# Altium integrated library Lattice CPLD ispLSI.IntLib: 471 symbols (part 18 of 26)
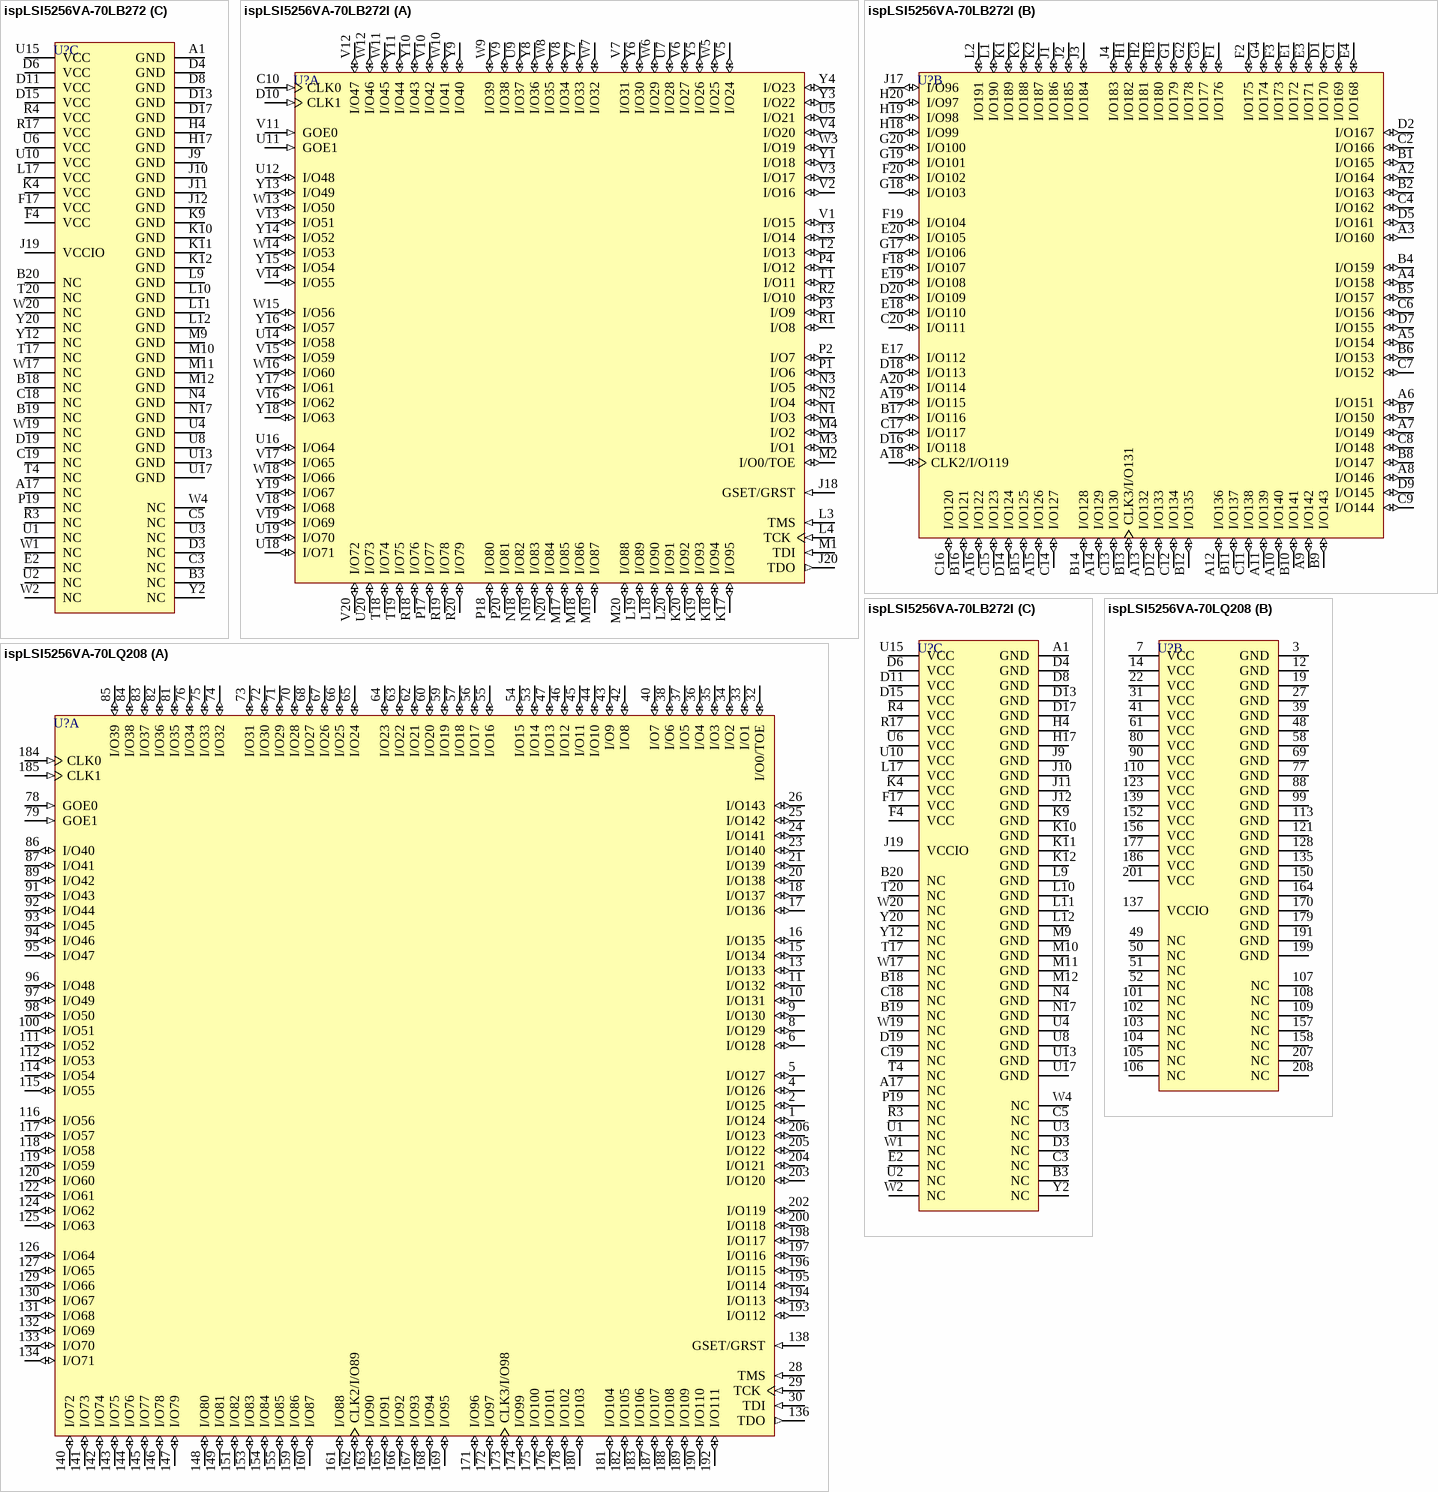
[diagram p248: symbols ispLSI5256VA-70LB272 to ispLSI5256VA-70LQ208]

## ispLSI5256VA-70LB272
designator U?
In-System Programmable 3.3V SuperWIDE High Density PLD
footprint BGA272 (BGA, 272-Leads, Body 27x27mm, Pitch 1.27mm)
3D model 5256VA-BGA272 (272-Ball Ball Grid Array (BGA272))
part A pins: C10 CLK0 (in), D10 CLK1 (in), J18 GSET/GRST (in), J20 TDO (out), K17 I/O95 (io), K18 I/O94 (io), K19 I/O93 (io), K20 I/O92 (io), L3 TMS (in), L4 TCK (in), L18 I/O90 (io), L19 I/O89 (io), L20 I/O91 (io), M1 TDI (in), M2 I/O0/TOE (io), M3 I/O1 (io), M4 I/O2 (io), M17 I/O85 (io), M18 I/O86 (io), M19 I/O87 (io), M20 I/O88 (io), N1 I/O3 (io), N2 I/O4 (io), N3 I/O5 (io), N18 I/O82 (io), N19 I/O83 (io), N20 I/O84 (io), P1 I/O6 (io), P2 I/O7 (io), P3 I/O9 (io), P4 I/O12 (io), P17 I/O77 (io), P18 I/O80 (io), P20 I/O81 (io), R1 I/O8 (io), R2 I/O10 (io), R18 I/O76 (io), R19 I/O78 (io), R20 I/O79 (io), T1 I/O11 (io), T2 I/O13 (io), T3 I/O14 (io), T18 I/O74 (io), T19 I/O75 (io), U5 I/O21 (io), U7 I/O28 (io), U9 I/O37 (io), U11 GOE1 (in), U12 I/O48 (io), U14 I/O58 (io), U16 I/O64 (io), U18 I/O71 (io), U19 I/O70 (io), U20 I/O73 (io), V1 I/O15 (io), V2 I/O16 (io), V3 I/O17 (io), V4 I/O20 (io), V5 I/O24 (io), V6 I/O27 (io), V7 I/O31 (io), V8 I/O34 (io), V9 I/O38 (io), V10 I/O42 (io), V11 GOE0 (in), V12 I/O47 (io), V13 I/O51 (io), V14 I/O55 (io), V15 I/O59 (io), V16 I/O62 (io), V17 I/O65 (io), V18 I/O68 (io), V19 I/O69 (io), V20 I/O72 (io), W3 I/O19 (io), W5 I/O25 (io), W6 I/O29 (io), W7 I/O32 (io), W8 I/O35 (io), W9 I/O39 (io), W10 I/O41 (io), W11 I/O45 (io), W12 I/O46 (io), W13 I/O50 (io), W14 I/O53 (io), W15 I/O56 (io), W16 I/O60 (io), W18 I/O66 (io), Y1 I/O18 (io), Y3 I/O22 (io), Y4 I/O23 (io), Y5 I/O26 (io), Y6 I/O30 (io), Y7 I/O33 (io), Y8 I/O36 (io), Y9 I/O40 (io), Y10 I/O43 (io), Y11 I/O44 (io), Y13 I/O49 (io), Y14 I/O52 (io), Y15 I/O54 (io), Y16 I/O57 (io), Y17 I/O61 (io), Y18 I/O63 (io), Y19 I/O67 (io)
part B pins: A2 I/O164 (io), A3 I/O160 (io), A4 I/O158 (io), A5 I/O154 (io), A6 I/O151 (io), A7 I/O149 (io), A8 I/O146 (io), A9 I/O142 (io), A10 I/O140 (io), A11 I/O139 (io), A12 I/O136 (io), A13 I/O132 (io), A14 I/O129 (io), A15 I/O126 (io), A16 I/O122 (io), A18 CLK2/I/O119 (io), A19 I/O115 (io), A20 I/O114 (io), B1 I/O165 (io), B2 I/O163 (io), B4 I/O159 (io), B5 I/O157 (io), B6 I/O153 (io), B7 I/O150 (io), B8 I/O147 (io), B9 I/O143 (io), B10 I/O141 (io), B11 I/O137 (io), B12 I/O135 (io), B13 CLK3/I/O131 (io), B14 I/O128 (io), B15 I/O125 (io), B16 I/O121 (io), B17 I/O116 (io), C1 I/O169 (io), C2 I/O166 (io), C4 I/O162 (io), C6 I/O156 (io), C7 I/O152 (io), C8 I/O148 (io), C9 I/O144 (io), C11 I/O138 (io), C12 I/O134 (io), C13 I/O130 (io), C14 I/O127 (io), C15 I/O123 (io), C16 I/O120 (io), C17 I/O117 (io), C20 I/O111 (io), D1 I/O170 (io), D2 I/O167 (io), D5 I/O161 (io), D7 I/O155 (io), D9 I/O145 (io), D12 I/O133 (io), D14 I/O124 (io), D16 I/O118 (io), D18 I/O113 (io), D20 I/O109 (io), E1 I/O172 (io), E3 I/O171 (io), E4 I/O168 (io), E17 I/O112 (io), E18 I/O110 (io), E19 I/O108 (io), E20 I/O105 (io), F1 I/O176 (io), F2 I/O175 (io), F3 I/O173 (io), F18 I/O107 (io), F19 I/O104 (io), F20 I/O102 (io), G1 I/O179 (io), G2 I/O178 (io), G3 I/O177 (io), G4 I/O174 (io), G17 I/O106 (io), G18 I/O103 (io), G19 I/O101 (io), G20 I/O100 (io), H1 I/O182 (io), H2 I/O181 (io), H3 I/O180 (io), H18 I/O99 (io), H19 I/O98 (io), H20 I/O97 (io), J1 I/O186 (io), J2 I/O185 (io), J3 I/O184 (io), J4 I/O183 (io), J17 I/O96 (io), K1 I/O189 (io), K2 I/O187 (io), K3 I/O188 (io), L1 I/O190 (io), L2 I/O191 (io)
part C pins: A1 GND (power), A17 NC, B3 NC, B18 NC, B19 NC, B20 NC, C3 NC, C5 NC, C18 NC, C19 NC, D3 NC, D4 GND (power), D6 VCC (power), D8 GND (power), D11 VCC (power), D13 GND (power), D15 VCC (power), D17 GND (power), D19 NC, E2 NC, F4 VCC (power), F17 VCC (power), H4 GND (power), H17 GND (power), J9 GND (power), J10 GND (power), J11 GND (power), J12 GND (power), J19 VCCIO (power), K4 VCC (power), K9 GND (power), K10 GND (power), K11 GND (power), K12 GND (power), L9 GND (power), L10 GND (power), L11 GND (power), L12 GND (power), L17 VCC (power), M9 GND (power), M10 GND (power), M11 GND (power), M12 GND (power), N4 GND (power), N17 GND (power), P19 NC, R3 NC, R4 VCC (power), R17 VCC (power), T4 NC, T17 NC, T20 NC, U1 NC, U2 NC, U3 NC, U4 GND (power), U6 VCC (power), U8 GND (power), U10 VCC (power), U13 GND (power), U15 VCC (power), U17 GND (power), W1 NC, W2 NC, W4 NC, W17 NC, W19 NC, W20 NC, Y2 NC, Y12 NC, Y20 NC

## ispLSI5256VA-70LB272I
designator U?
In-System Programmable 3.3V SuperWIDE High Density PLD
footprint BGA272 (BGA, 272-Leads, Body 27x27mm, Pitch 1.27mm)
3D model 5256VA-BGA272 (272-Ball Ball Grid Array (BGA272))
part A pins: C10 CLK0 (in), D10 CLK1 (in), J18 GSET/GRST (in), J20 TDO (out), K17 I/O95 (io), K18 I/O94 (io), K19 I/O93 (io), K20 I/O92 (io), L3 TMS (in), L4 TCK (in), L18 I/O90 (io), L19 I/O89 (io), L20 I/O91 (io), M1 TDI (in), M2 I/O0/TOE (io), M3 I/O1 (io), M4 I/O2 (io), M17 I/O85 (io), M18 I/O86 (io), M19 I/O87 (io), M20 I/O88 (io), N1 I/O3 (io), N2 I/O4 (io), N3 I/O5 (io), N18 I/O82 (io), N19 I/O83 (io), N20 I/O84 (io), P1 I/O6 (io), P2 I/O7 (io), P3 I/O9 (io), P4 I/O12 (io), P17 I/O77 (io), P18 I/O80 (io), P20 I/O81 (io), R1 I/O8 (io), R2 I/O10 (io), R18 I/O76 (io), R19 I/O78 (io), R20 I/O79 (io), T1 I/O11 (io), T2 I/O13 (io), T3 I/O14 (io), T18 I/O74 (io), T19 I/O75 (io), U5 I/O21 (io), U7 I/O28 (io), U9 I/O37 (io), U11 GOE1 (in), U12 I/O48 (io), U14 I/O58 (io), U16 I/O64 (io), U18 I/O71 (io), U19 I/O70 (io), U20 I/O73 (io), V1 I/O15 (io), V2 I/O16 (io), V3 I/O17 (io), V4 I/O20 (io), V5 I/O24 (io), V6 I/O27 (io), V7 I/O31 (io), V8 I/O34 (io), V9 I/O38 (io), V10 I/O42 (io), V11 GOE0 (in), V12 I/O47 (io), V13 I/O51 (io), V14 I/O55 (io), V15 I/O59 (io), V16 I/O62 (io), V17 I/O65 (io), V18 I/O68 (io), V19 I/O69 (io), V20 I/O72 (io), W3 I/O19 (io), W5 I/O25 (io), W6 I/O29 (io), W7 I/O32 (io), W8 I/O35 (io), W9 I/O39 (io), W10 I/O41 (io), W11 I/O45 (io), W12 I/O46 (io), W13 I/O50 (io), W14 I/O53 (io), W15 I/O56 (io), W16 I/O60 (io), W18 I/O66 (io), Y1 I/O18 (io), Y3 I/O22 (io), Y4 I/O23 (io), Y5 I/O26 (io), Y6 I/O30 (io), Y7 I/O33 (io), Y8 I/O36 (io), Y9 I/O40 (io), Y10 I/O43 (io), Y11 I/O44 (io), Y13 I/O49 (io), Y14 I/O52 (io), Y15 I/O54 (io), Y16 I/O57 (io), Y17 I/O61 (io), Y18 I/O63 (io), Y19 I/O67 (io)
part B pins: A2 I/O164 (io), A3 I/O160 (io), A4 I/O158 (io), A5 I/O154 (io), A6 I/O151 (io), A7 I/O149 (io), A8 I/O146 (io), A9 I/O142 (io), A10 I/O140 (io), A11 I/O139 (io), A12 I/O136 (io), A13 I/O132 (io), A14 I/O129 (io), A15 I/O126 (io), A16 I/O122 (io), A18 CLK2/I/O119 (io), A19 I/O115 (io), A20 I/O114 (io), B1 I/O165 (io), B2 I/O163 (io), B4 I/O159 (io), B5 I/O157 (io), B6 I/O153 (io), B7 I/O150 (io), B8 I/O147 (io), B9 I/O143 (io), B10 I/O141 (io), B11 I/O137 (io), B12 I/O135 (io), B13 CLK3/I/O131 (io), B14 I/O128 (io), B15 I/O125 (io), B16 I/O121 (io), B17 I/O116 (io), C1 I/O169 (io), C2 I/O166 (io), C4 I/O162 (io), C6 I/O156 (io), C7 I/O152 (io), C8 I/O148 (io), C9 I/O144 (io), C11 I/O138 (io), C12 I/O134 (io), C13 I/O130 (io), C14 I/O127 (io), C15 I/O123 (io), C16 I/O120 (io), C17 I/O117 (io), C20 I/O111 (io), D1 I/O170 (io), D2 I/O167 (io), D5 I/O161 (io), D7 I/O155 (io), D9 I/O145 (io), D12 I/O133 (io), D14 I/O124 (io), D16 I/O118 (io), D18 I/O113 (io), D20 I/O109 (io), E1 I/O172 (io), E3 I/O171 (io), E4 I/O168 (io), E17 I/O112 (io), E18 I/O110 (io), E19 I/O108 (io), E20 I/O105 (io), F1 I/O176 (io), F2 I/O175 (io), F3 I/O173 (io), F18 I/O107 (io), F19 I/O104 (io), F20 I/O102 (io), G1 I/O179 (io), G2 I/O178 (io), G3 I/O177 (io), G4 I/O174 (io), G17 I/O106 (io), G18 I/O103 (io), G19 I/O101 (io), G20 I/O100 (io), H1 I/O182 (io), H2 I/O181 (io), H3 I/O180 (io), H18 I/O99 (io), H19 I/O98 (io), H20 I/O97 (io), J1 I/O186 (io), J2 I/O185 (io), J3 I/O184 (io), J4 I/O183 (io), J17 I/O96 (io), K1 I/O189 (io), K2 I/O187 (io), K3 I/O188 (io), L1 I/O190 (io), L2 I/O191 (io)
part C pins: A1 GND (power), A17 NC, B3 NC, B18 NC, B19 NC, B20 NC, C3 NC, C5 NC, C18 NC, C19 NC, D3 NC, D4 GND (power), D6 VCC (power), D8 GND (power), D11 VCC (power), D13 GND (power), D15 VCC (power), D17 GND (power), D19 NC, E2 NC, F4 VCC (power), F17 VCC (power), H4 GND (power), H17 GND (power), J9 GND (power), J10 GND (power), J11 GND (power), J12 GND (power), J19 VCCIO (power), K4 VCC (power), K9 GND (power), K10 GND (power), K11 GND (power), K12 GND (power), L9 GND (power), L10 GND (power), L11 GND (power), L12 GND (power), L17 VCC (power), M9 GND (power), M10 GND (power), M11 GND (power), M12 GND (power), N4 GND (power), N17 GND (power), P19 NC, R3 NC, R4 VCC (power), R17 VCC (power), T4 NC, T17 NC, T20 NC, U1 NC, U2 NC, U3 NC, U4 GND (power), U6 VCC (power), U8 GND (power), U10 VCC (power), U13 GND (power), U15 VCC (power), U17 GND (power), W1 NC, W2 NC, W4 NC, W17 NC, W19 NC, W20 NC, Y2 NC, Y12 NC, Y20 NC

## ispLSI5256VA-70LQ208
designator U?
In-System Programmable 3.3V SuperWIDE High Density PLD
footprint PQFP208_N (Shrink QFP, 208-Leads, Body 28x28mm, Pitch 0.5mm, IPC Medium Density)
footprint PQFP208_L (Shrink QFP, 208-Leads, Body 28x28mm, Pitch 0.5mm, IPC High Density)
footprint PQFP208_M (Shrink QFP, 208-Leads, Body 28x28mm, Pitch 0.5mm, IPC Low Density)
3D model 5256VA-PQFP208 (208-Pin Plastic Quad Flat Pack (PQFP208))
part A pins: 1 I/O124 (io), 2 I/O125 (io), 4 I/O126 (io), 5 I/O127 (io), 6 I/O128 (io), 8 I/O129 (io), 9 I/O130 (io), 10 I/O131 (io), 11 I/O132 (io), 13 I/O133 (io), 15 I/O134 (io), 16 I/O135 (io), 17 I/O136 (io), 18 I/O137 (io), 20 I/O138 (io), 21 I/O139 (io), 23 I/O140 (io), 24 I/O141 (io), 25 I/O142 (io), 26 I/O143 (io), 28 TMS (in), 29 TCK (in), 30 TDI (in), 32 I/O0/TOE (io), 33 I/O1 (io), 34 I/O2 (io), 35 I/O3 (io), 36 I/O4 (io), 37 I/O5 (io), 38 I/O6 (io), 40 I/O7 (io), 42 I/O8 (io), 43 I/O9 (io), 44 I/O10 (io), 45 I/O11 (io), 46 I/O12 (io), 47 I/O13 (io), 53 I/O14 (io), 54 I/O15 (io), 55 I/O16 (io), 56 I/O17 (io), 57 I/O18 (io), 59 I/O19 (io), 60 I/O20 (io), 62 I/O21 (io), 63 I/O22 (io), 64 I/O23 (io), 65 I/O24 (io), 66 I/O25 (io), 67 I/O26 (io), 68 I/O27 (io), 70 I/O28 (io), 71 I/O29 (io), 72 I/O30 (io), 73 I/O31 (io), 74 I/O32 (io), 75 I/O33 (io), 76 I/O34 (io), 78 GOE0 (in), 79 GOE1 (in), 81 I/O35 (io), 82 I/O36 (io), 83 I/O37 (io), 84 I/O38 (io), 85 I/O39 (io), 86 I/O40 (io), 87 I/O41 (io), 89 I/O42 (io), 91 I/O43 (io), 92 I/O44 (io), 93 I/O45 (io), 94 I/O46 (io), 95 I/O47 (io), 96 I/O48 (io), 97 I/O49 (io), 98 I/O50 (io), 100 I/O51 (io), 111 I/O52 (io), 112 I/O53 (io), 114 I/O54 (io), 115 I/O55 (io), 116 I/O56 (io), 117 I/O57 (io), 118 I/O58 (io), 119 I/O59 (io), 120 I/O60 (io), 122 I/O61 (io), 124 I/O62 (io), 125 I/O63 (io), 126 I/O64 (io), 127 I/O65 (io), 129 I/O66 (io), 130 I/O67 (io), 131 I/O68 (io), 132 I/O69 (io), 133 I/O70 (io), 134 I/O71 (io), 136 TDO (out), 138 GSET/GRST (in), 140 I/O72 (io), 141 I/O73 (io), 142 I/O74 (io), 143 I/O75 (io), 144 I/O76 (io), 145 I/O77 (io), 146 I/O78 (io), 147 I/O79 (io), 148 I/O80 (io), 149 I/O81 (io), 151 I/O82 (io), 153 I/O83 (io), 154 I/O84 (io), 155 I/O85 (io), 159 I/O86 (io), 160 I/O87 (io), 161 I/O88 (io), 162 CLK2/I/O89 (io), 163 I/O90 (io), 165 I/O91 (io), 166 I/O92 (io), 167 I/O93 (io), 168 I/O94 (io), 169 I/O95 (io), 171 I/O96 (io), 172 I/O97 (io), 173 CLK3/I/O98 (io), 174 I/O99 (io), 175 I/O100 (io), 176 I/O101 (io), 178 I/O102 (io), 180 I/O103 (io), 181 I/O104 (io), 182 I/O105 (io), 183 I/O106 (io), 184 CLK0 (in), 185 CLK1 (in), 187 I/O107 (io), 188 I/O108 (io), 189 I/O109 (io), 190 I/O110 (io), 192 I/O111 (io), 193 I/O112 (io), 194 I/O113 (io), 195 I/O114 (io), 196 I/O115 (io), 197 I/O116 (io), 198 I/O117 (io), 200 I/O118 (io), 202 I/O119 (io), 203 I/O120 (io), 204 I/O121 (io), 205 I/O122 (io), 206 I/O123 (io)
part B pins: 3 GND (power), 7 VCC (power), 12 GND (power), 14 VCC (power), 19 GND (power), 22 VCC (power), 27 GND (power), 31 VCC (power), 39 GND (power), 41 VCC (power), 48 GND (power), 49 NC, 50 NC, 51 NC, 52 NC, 58 GND (power), 61 VCC (power), 69 GND (power), 77 GND (power), 80 VCC (power), 88 GND (power), 90 VCC (power), 99 GND (power), 101 NC, 102 NC, 103 NC, 104 NC, 105 NC, 106 NC, 107 NC, 108 NC, 109 NC, 110 VCC (power), 113 GND (power), 121 GND (power), 123 VCC (power), 128 GND (power), 135 GND (power), 137 VCCIO (power), 139 VCC (power), 150 GND (power), 152 VCC (power), 156 VCC (power), 157 NC, 158 NC, 164 GND (power), 170 GND (power), 177 VCC (power), 179 GND (power), 186 VCC (power), 191 GND (power), 199 GND (power), 201 VCC (power), 207 NC, 208 NC

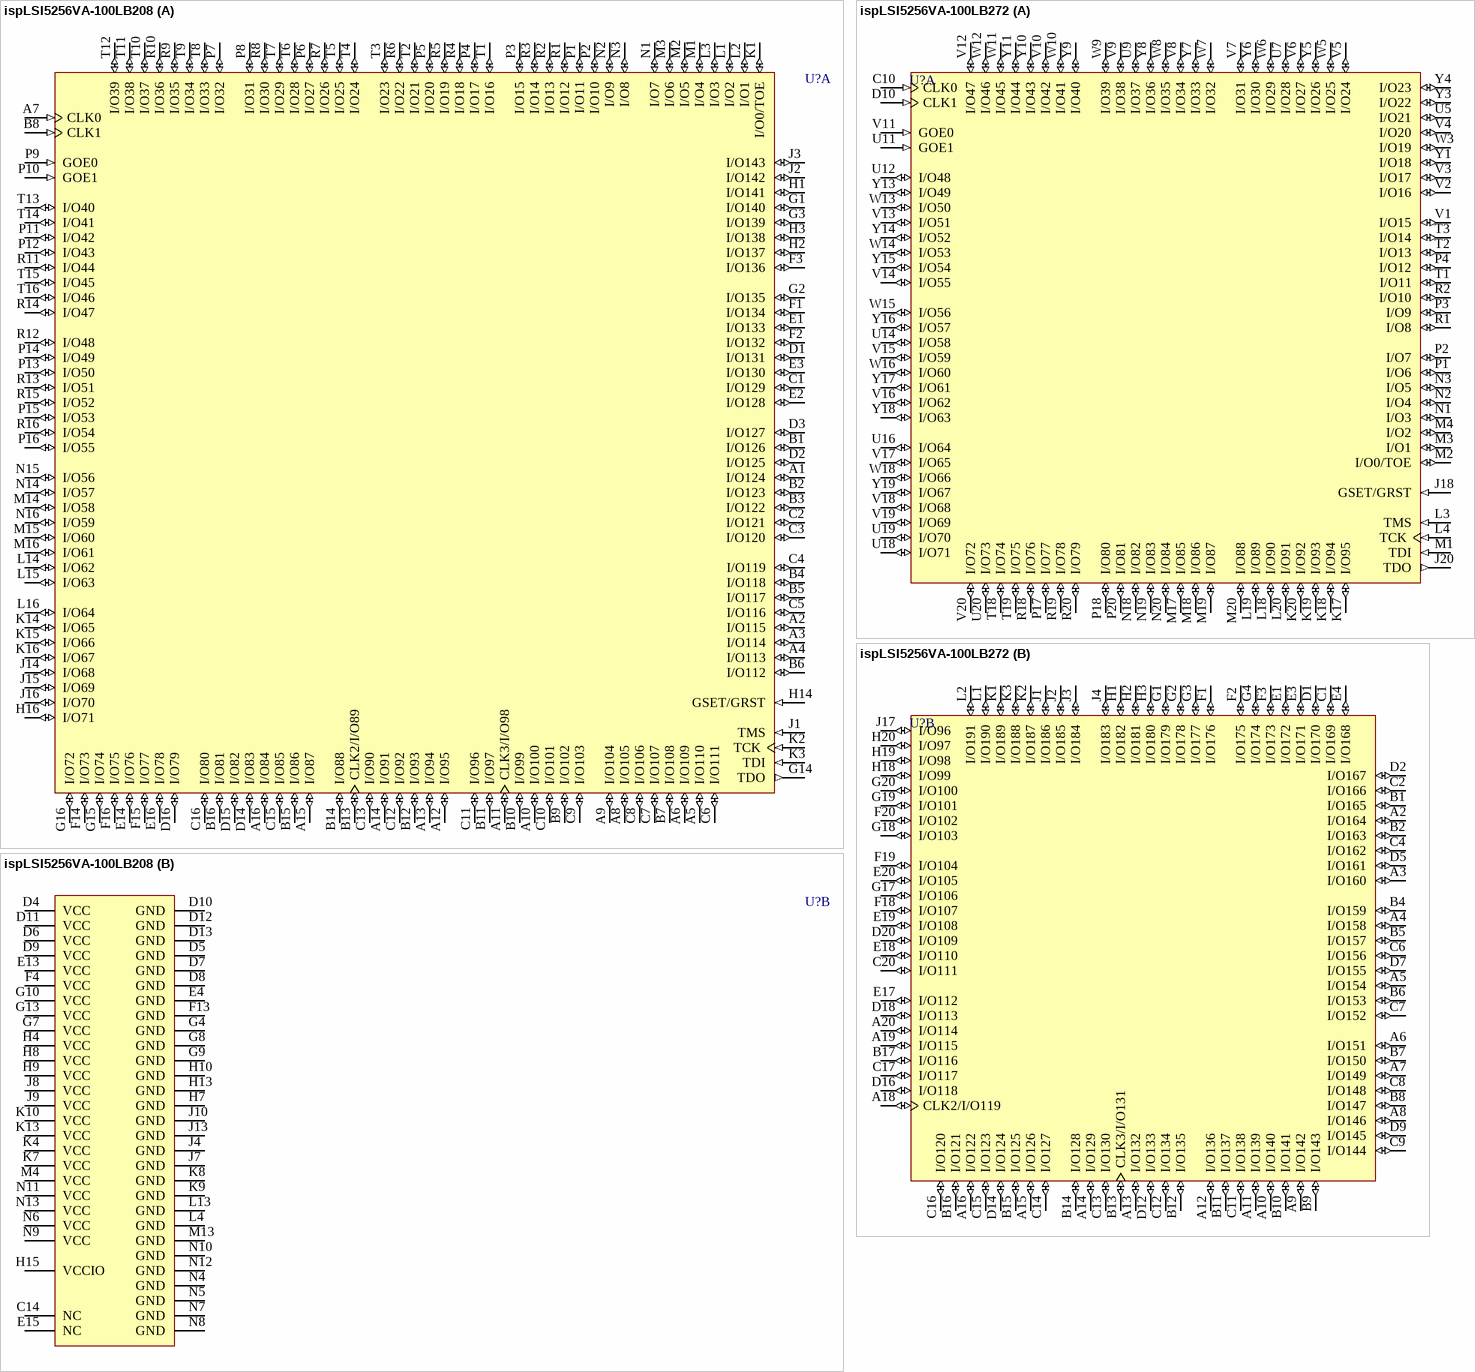
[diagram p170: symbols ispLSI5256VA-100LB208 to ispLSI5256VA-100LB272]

## ispLSI5256VA-100LB208
designator U?
In-System Programmable 3.3V SuperWIDE High Density PLD
footprint fpBGA208 (BGA, 208-Leads, Body 17x17mm, Pitch 1mm)
3D model 5384VA-fpBGA208 (208-Ball Fine Pitch Ball Grid Array (fpBGA208))
part A pins: A1 I/O124 (io), A2 I/O115 (io), A3 I/O114 (io), A4 I/O113 (io), A5 I/O110 (io), A6 I/O109 (io), A7 CLK0 (in), A8 I/O105 (io), A9 I/O104 (io), A10 I/O100 (io), A11 CLK3/I/O98 (io), A12 I/O95 (io), A13 I/O94 (io), A14 I/O91 (io), A15 I/O87 (io), A16 I/O84 (io), B1 I/O126 (io), B2 I/O123 (io), B3 I/O122 (io), B4 I/O118 (io), B5 I/O117 (io), B6 I/O112 (io), B7 I/O108 (io), B8 CLK1 (in), B9 I/O102 (io), B10 I/O99 (io), B11 I/O97 (io), B12 I/O93 (io), B13 CLK2/I/O89 (io), B14 I/O88 (io), B15 I/O86 (io), B16 I/O81 (io), C1 I/O129 (io), C2 I/O121 (io), C3 I/O120 (io), C4 I/O119 (io), C5 I/O116 (io), C6 I/O111 (io), C7 I/O107 (io), C8 I/O106 (io), C9 I/O103 (io), C10 I/O101 (io), C11 I/O96 (io), C12 I/O92 (io), C13 I/O90 (io), C15 I/O85 (io), C16 I/O80 (io), D1 I/O131 (io), D2 I/O125 (io), D3 I/O127 (io), D14 I/O83 (io), D15 I/O82 (io), D16 I/O79 (io), E1 I/O133 (io), E2 I/O128 (io), E3 I/O130 (io), E14 I/O76 (io), E16 I/O78 (io), F1 I/O134 (io), F2 I/O132 (io), F3 I/O136 (io), F14 I/O73 (io), F15 I/O77 (io), F16 I/O75 (io), G1 I/O140 (io), G2 I/O135 (io), G3 I/O139 (io), G14 TDO (out), G15 I/O74 (io), G16 I/O72 (io), H1 I/O141 (io), H2 I/O137 (io), H3 I/O138 (io), H14 GSET/GRST (in), H16 I/O71 (io), J1 TMS (in), J2 I/O142 (io), J3 I/O143 (io), J14 I/O68 (io), J15 I/O69 (io), J16 I/O70 (io), K1 I/O0/TOE (io), K2 TCK (in), K3 TDI (in), K14 I/O65 (io), K15 I/O66 (io), K16 I/O67 (io), L1 I/O2 (io), L2 I/O1 (io), L3 I/O3 (io), L14 I/O62 (io), L15 I/O63 (io), L16 I/O64 (io), M1 I/O4 (io), M2 I/O5 (io), M3 I/O6 (io), M14 I/O58 (io), M15 I/O60 (io), M16 I/O61 (io), N1 I/O7 (io), N2 I/O9 (io), N3 I/O8 (io), N14 I/O57 (io), N15 I/O56 (io), N16 I/O59 (io), P1 I/O11 (io), P2 I/O10 (io), P3 I/O15 (io), P4 I/O17 (io), P5 I/O20 (io), P6 I/O27 (io), P7 I/O32 (io), P8 I/O31 (io), P9 GOE0 (in), P10 GOE1 (in), P11 I/O42 (io), P12 I/O43 (io), P13 I/O50 (io), P14 I/O49 (io), P15 I/O53 (io), P16 I/O55 (io), R1 I/O12 (io), R2 I/O13 (io), R3 I/O14 (io), R4 I/O18 (io), R5 I/O19 (io), R6 I/O22 (io), R7 I/O26 (io), R8 I/O30 (io), R9 I/O35 (io), R10 I/O36 (io), R11 I/O44 (io), R12 I/O48 (io), R13 I/O51 (io), R14 I/O47 (io), R15 I/O52 (io), R16 I/O54 (io), T1 I/O16 (io), T2 I/O21 (io), T3 I/O23 (io), T4 I/O24 (io), T5 I/O25 (io), T6 I/O28 (io), T7 I/O29 (io), T8 I/O33 (io), T9 I/O34 (io), T10 I/O37 (io), T11 I/O38 (io), T12 I/O39 (io), T13 I/O40 (io), T14 I/O41 (io), T15 I/O45 (io), T16 I/O46 (io)
part B pins: C14 NC, D4 VCC (power), D5 GND (power), D6 VCC (power), D7 GND (power), D8 GND (power), D9 VCC (power), D10 GND (power), D11 VCC (power), D12 GND (power), D13 GND (power), E4 GND (power), E13 VCC (power), E15 NC, F4 VCC (power), F13 GND (power), G4 GND (power), G7 VCC (power), G8 GND (power), G9 GND (power), G10 VCC (power), G13 VCC (power), H4 VCC (power), H7 GND (power), H8 VCC (power), H9 VCC (power), H10 GND (power), H13 GND (power), H15 VCCIO (power), J4 GND (power), J7 GND (power), J8 VCC (power), J9 VCC (power), J10 GND (power), J13 GND (power), K4 VCC (power), K7 VCC (power), K8 GND (power), K9 GND (power), K10 VCC (power), K13 VCC (power), L4 GND (power), L13 GND (power), M4 VCC (power), M13 GND (power), N4 GND (power), N5 GND (power), N6 VCC (power), N7 GND (power), N8 GND (power), N9 VCC (power), N10 GND (power), N11 VCC (power), N12 GND (power), N13 VCC (power)

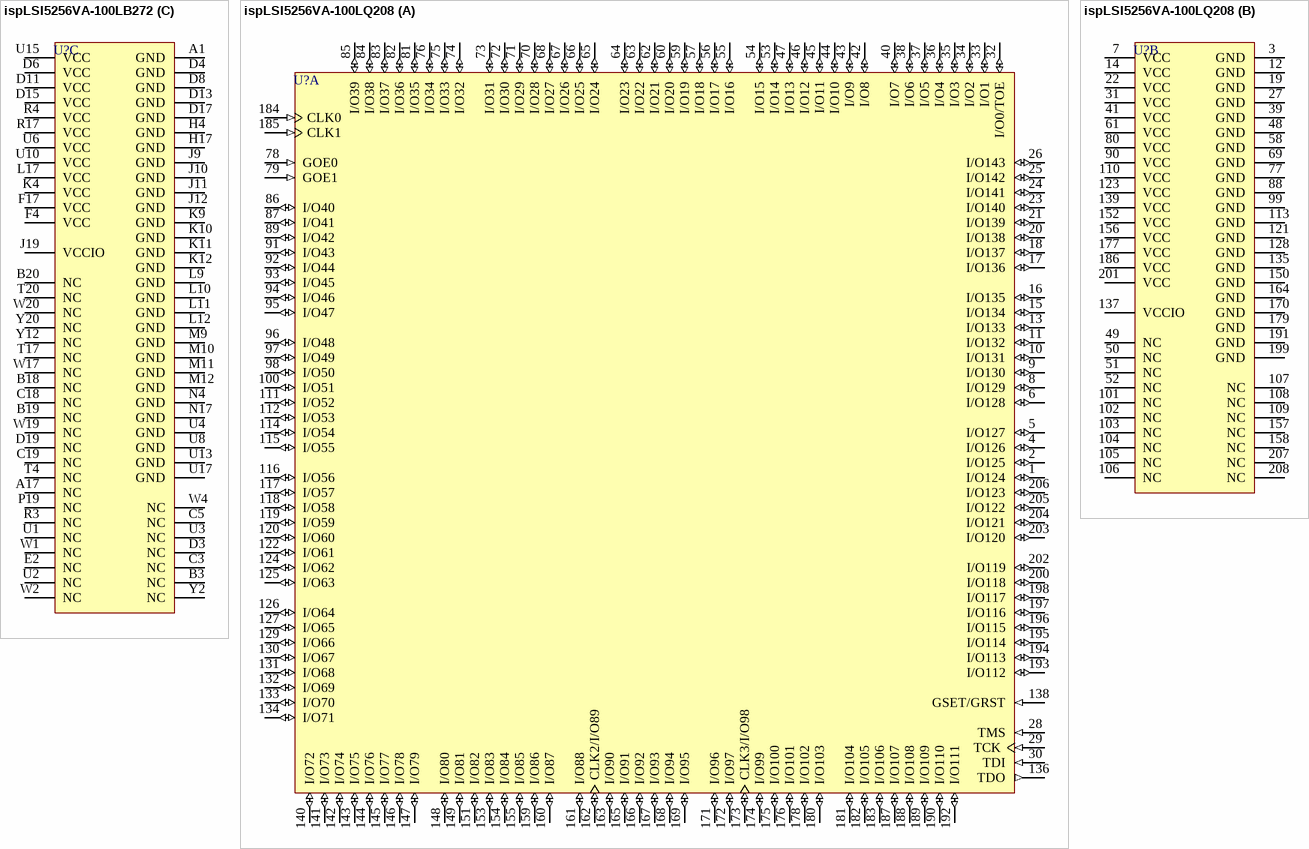
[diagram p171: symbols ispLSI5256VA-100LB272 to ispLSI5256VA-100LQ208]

## ispLSI5256VA-100LB272
designator U?
In-System Programmable 3.3V SuperWIDE High Density PLD
footprint BGA272 (BGA, 272-Leads, Body 27x27mm, Pitch 1.27mm)
3D model 5256VA-BGA272 (272-Ball Ball Grid Array (BGA272))
part A pins: C10 CLK0 (in), D10 CLK1 (in), J18 GSET/GRST (in), J20 TDO (out), K17 I/O95 (io), K18 I/O94 (io), K19 I/O93 (io), K20 I/O92 (io), L3 TMS (in), L4 TCK (in), L18 I/O90 (io), L19 I/O89 (io), L20 I/O91 (io), M1 TDI (in), M2 I/O0/TOE (io), M3 I/O1 (io), M4 I/O2 (io), M17 I/O85 (io), M18 I/O86 (io), M19 I/O87 (io), M20 I/O88 (io), N1 I/O3 (io), N2 I/O4 (io), N3 I/O5 (io), N18 I/O82 (io), N19 I/O83 (io), N20 I/O84 (io), P1 I/O6 (io), P2 I/O7 (io), P3 I/O9 (io), P4 I/O12 (io), P17 I/O77 (io), P18 I/O80 (io), P20 I/O81 (io), R1 I/O8 (io), R2 I/O10 (io), R18 I/O76 (io), R19 I/O78 (io), R20 I/O79 (io), T1 I/O11 (io), T2 I/O13 (io), T3 I/O14 (io), T18 I/O74 (io), T19 I/O75 (io), U5 I/O21 (io), U7 I/O28 (io), U9 I/O37 (io), U11 GOE1 (in), U12 I/O48 (io), U14 I/O58 (io), U16 I/O64 (io), U18 I/O71 (io), U19 I/O70 (io), U20 I/O73 (io), V1 I/O15 (io), V2 I/O16 (io), V3 I/O17 (io), V4 I/O20 (io), V5 I/O24 (io), V6 I/O27 (io), V7 I/O31 (io), V8 I/O34 (io), V9 I/O38 (io), V10 I/O42 (io), V11 GOE0 (in), V12 I/O47 (io), V13 I/O51 (io), V14 I/O55 (io), V15 I/O59 (io), V16 I/O62 (io), V17 I/O65 (io), V18 I/O68 (io), V19 I/O69 (io), V20 I/O72 (io), W3 I/O19 (io), W5 I/O25 (io), W6 I/O29 (io), W7 I/O32 (io), W8 I/O35 (io), W9 I/O39 (io), W10 I/O41 (io), W11 I/O45 (io), W12 I/O46 (io), W13 I/O50 (io), W14 I/O53 (io), W15 I/O56 (io), W16 I/O60 (io), W18 I/O66 (io), Y1 I/O18 (io), Y3 I/O22 (io), Y4 I/O23 (io), Y5 I/O26 (io), Y6 I/O30 (io), Y7 I/O33 (io), Y8 I/O36 (io), Y9 I/O40 (io), Y10 I/O43 (io), Y11 I/O44 (io), Y13 I/O49 (io), Y14 I/O52 (io), Y15 I/O54 (io), Y16 I/O57 (io), Y17 I/O61 (io), Y18 I/O63 (io), Y19 I/O67 (io)
part B pins: A2 I/O164 (io), A3 I/O160 (io), A4 I/O158 (io), A5 I/O154 (io), A6 I/O151 (io), A7 I/O149 (io), A8 I/O146 (io), A9 I/O142 (io), A10 I/O140 (io), A11 I/O139 (io), A12 I/O136 (io), A13 I/O132 (io), A14 I/O129 (io), A15 I/O126 (io), A16 I/O122 (io), A18 CLK2/I/O119 (io), A19 I/O115 (io), A20 I/O114 (io), B1 I/O165 (io), B2 I/O163 (io), B4 I/O159 (io), B5 I/O157 (io), B6 I/O153 (io), B7 I/O150 (io), B8 I/O147 (io), B9 I/O143 (io), B10 I/O141 (io), B11 I/O137 (io), B12 I/O135 (io), B13 CLK3/I/O131 (io), B14 I/O128 (io), B15 I/O125 (io), B16 I/O121 (io), B17 I/O116 (io), C1 I/O169 (io), C2 I/O166 (io), C4 I/O162 (io), C6 I/O156 (io), C7 I/O152 (io), C8 I/O148 (io), C9 I/O144 (io), C11 I/O138 (io), C12 I/O134 (io), C13 I/O130 (io), C14 I/O127 (io), C15 I/O123 (io), C16 I/O120 (io), C17 I/O117 (io), C20 I/O111 (io), D1 I/O170 (io), D2 I/O167 (io), D5 I/O161 (io), D7 I/O155 (io), D9 I/O145 (io), D12 I/O133 (io), D14 I/O124 (io), D16 I/O118 (io), D18 I/O113 (io), D20 I/O109 (io), E1 I/O172 (io), E3 I/O171 (io), E4 I/O168 (io), E17 I/O112 (io), E18 I/O110 (io), E19 I/O108 (io), E20 I/O105 (io), F1 I/O176 (io), F2 I/O175 (io), F3 I/O173 (io), F18 I/O107 (io), F19 I/O104 (io), F20 I/O102 (io), G1 I/O179 (io), G2 I/O178 (io), G3 I/O177 (io), G4 I/O174 (io), G17 I/O106 (io), G18 I/O103 (io), G19 I/O101 (io), G20 I/O100 (io), H1 I/O182 (io), H2 I/O181 (io), H3 I/O180 (io), H18 I/O99 (io), H19 I/O98 (io), H20 I/O97 (io), J1 I/O186 (io), J2 I/O185 (io), J3 I/O184 (io), J4 I/O183 (io), J17 I/O96 (io), K1 I/O189 (io), K2 I/O187 (io), K3 I/O188 (io), L1 I/O190 (io), L2 I/O191 (io)
part C pins: A1 GND (power), A17 NC, B3 NC, B18 NC, B19 NC, B20 NC, C3 NC, C5 NC, C18 NC, C19 NC, D3 NC, D4 GND (power), D6 VCC (power), D8 GND (power), D11 VCC (power), D13 GND (power), D15 VCC (power), D17 GND (power), D19 NC, E2 NC, F4 VCC (power), F17 VCC (power), H4 GND (power), H17 GND (power), J9 GND (power), J10 GND (power), J11 GND (power), J12 GND (power), J19 VCCIO (power), K4 VCC (power), K9 GND (power), K10 GND (power), K11 GND (power), K12 GND (power), L9 GND (power), L10 GND (power), L11 GND (power), L12 GND (power), L17 VCC (power), M9 GND (power), M10 GND (power), M11 GND (power), M12 GND (power), N4 GND (power), N17 GND (power), P19 NC, R3 NC, R4 VCC (power), R17 VCC (power), T4 NC, T17 NC, T20 NC, U1 NC, U2 NC, U3 NC, U4 GND (power), U6 VCC (power), U8 GND (power), U10 VCC (power), U13 GND (power), U15 VCC (power), U17 GND (power), W1 NC, W2 NC, W4 NC, W17 NC, W19 NC, W20 NC, Y2 NC, Y12 NC, Y20 NC

## ispLSI5256VA-100LQ208
designator U?
In-System Programmable 3.3V SuperWIDE High Density PLD
footprint PQFP208_N (Shrink QFP, 208-Leads, Body 28x28mm, Pitch 0.5mm, IPC Medium Density)
footprint PQFP208_L (Shrink QFP, 208-Leads, Body 28x28mm, Pitch 0.5mm, IPC High Density)
footprint PQFP208_M (Shrink QFP, 208-Leads, Body 28x28mm, Pitch 0.5mm, IPC Low Density)
3D model 5256VA-PQFP208 (208-Pin Plastic Quad Flat Pack (PQFP208))
part A pins: 1 I/O124 (io), 2 I/O125 (io), 4 I/O126 (io), 5 I/O127 (io), 6 I/O128 (io), 8 I/O129 (io), 9 I/O130 (io), 10 I/O131 (io), 11 I/O132 (io), 13 I/O133 (io), 15 I/O134 (io), 16 I/O135 (io), 17 I/O136 (io), 18 I/O137 (io), 20 I/O138 (io), 21 I/O139 (io), 23 I/O140 (io), 24 I/O141 (io), 25 I/O142 (io), 26 I/O143 (io), 28 TMS (in), 29 TCK (in), 30 TDI (in), 32 I/O0/TOE (io), 33 I/O1 (io), 34 I/O2 (io), 35 I/O3 (io), 36 I/O4 (io), 37 I/O5 (io), 38 I/O6 (io), 40 I/O7 (io), 42 I/O8 (io), 43 I/O9 (io), 44 I/O10 (io), 45 I/O11 (io), 46 I/O12 (io), 47 I/O13 (io), 53 I/O14 (io), 54 I/O15 (io), 55 I/O16 (io), 56 I/O17 (io), 57 I/O18 (io), 59 I/O19 (io), 60 I/O20 (io), 62 I/O21 (io), 63 I/O22 (io), 64 I/O23 (io), 65 I/O24 (io), 66 I/O25 (io), 67 I/O26 (io), 68 I/O27 (io), 70 I/O28 (io), 71 I/O29 (io), 72 I/O30 (io), 73 I/O31 (io), 74 I/O32 (io), 75 I/O33 (io), 76 I/O34 (io), 78 GOE0 (in), 79 GOE1 (in), 81 I/O35 (io), 82 I/O36 (io), 83 I/O37 (io), 84 I/O38 (io), 85 I/O39 (io), 86 I/O40 (io), 87 I/O41 (io), 89 I/O42 (io), 91 I/O43 (io), 92 I/O44 (io), 93 I/O45 (io), 94 I/O46 (io), 95 I/O47 (io), 96 I/O48 (io), 97 I/O49 (io), 98 I/O50 (io), 100 I/O51 (io), 111 I/O52 (io), 112 I/O53 (io), 114 I/O54 (io), 115 I/O55 (io), 116 I/O56 (io), 117 I/O57 (io), 118 I/O58 (io), 119 I/O59 (io), 120 I/O60 (io), 122 I/O61 (io), 124 I/O62 (io), 125 I/O63 (io), 126 I/O64 (io), 127 I/O65 (io), 129 I/O66 (io), 130 I/O67 (io), 131 I/O68 (io), 132 I/O69 (io), 133 I/O70 (io), 134 I/O71 (io), 136 TDO (out), 138 GSET/GRST (in), 140 I/O72 (io), 141 I/O73 (io), 142 I/O74 (io), 143 I/O75 (io), 144 I/O76 (io), 145 I/O77 (io), 146 I/O78 (io), 147 I/O79 (io), 148 I/O80 (io), 149 I/O81 (io), 151 I/O82 (io), 153 I/O83 (io), 154 I/O84 (io), 155 I/O85 (io), 159 I/O86 (io), 160 I/O87 (io), 161 I/O88 (io), 162 CLK2/I/O89 (io), 163 I/O90 (io), 165 I/O91 (io), 166 I/O92 (io), 167 I/O93 (io), 168 I/O94 (io), 169 I/O95 (io), 171 I/O96 (io), 172 I/O97 (io), 173 CLK3/I/O98 (io), 174 I/O99 (io), 175 I/O100 (io), 176 I/O101 (io), 178 I/O102 (io), 180 I/O103 (io), 181 I/O104 (io), 182 I/O105 (io), 183 I/O106 (io), 184 CLK0 (in), 185 CLK1 (in), 187 I/O107 (io), 188 I/O108 (io), 189 I/O109 (io), 190 I/O110 (io), 192 I/O111 (io), 193 I/O112 (io), 194 I/O113 (io), 195 I/O114 (io), 196 I/O115 (io), 197 I/O116 (io), 198 I/O117 (io), 200 I/O118 (io), 202 I/O119 (io), 203 I/O120 (io), 204 I/O121 (io), 205 I/O122 (io), 206 I/O123 (io)
part B pins: 3 GND (power), 7 VCC (power), 12 GND (power), 14 VCC (power), 19 GND (power), 22 VCC (power), 27 GND (power), 31 VCC (power), 39 GND (power), 41 VCC (power), 48 GND (power), 49 NC, 50 NC, 51 NC, 52 NC, 58 GND (power), 61 VCC (power), 69 GND (power), 77 GND (power), 80 VCC (power), 88 GND (power), 90 VCC (power), 99 GND (power), 101 NC, 102 NC, 103 NC, 104 NC, 105 NC, 106 NC, 107 NC, 108 NC, 109 NC, 110 VCC (power), 113 GND (power), 121 GND (power), 123 VCC (power), 128 GND (power), 135 GND (power), 137 VCCIO (power), 139 VCC (power), 150 GND (power), 152 VCC (power), 156 VCC (power), 157 NC, 158 NC, 164 GND (power), 170 GND (power), 177 VCC (power), 179 GND (power), 186 VCC (power), 191 GND (power), 199 GND (power), 201 VCC (power), 207 NC, 208 NC

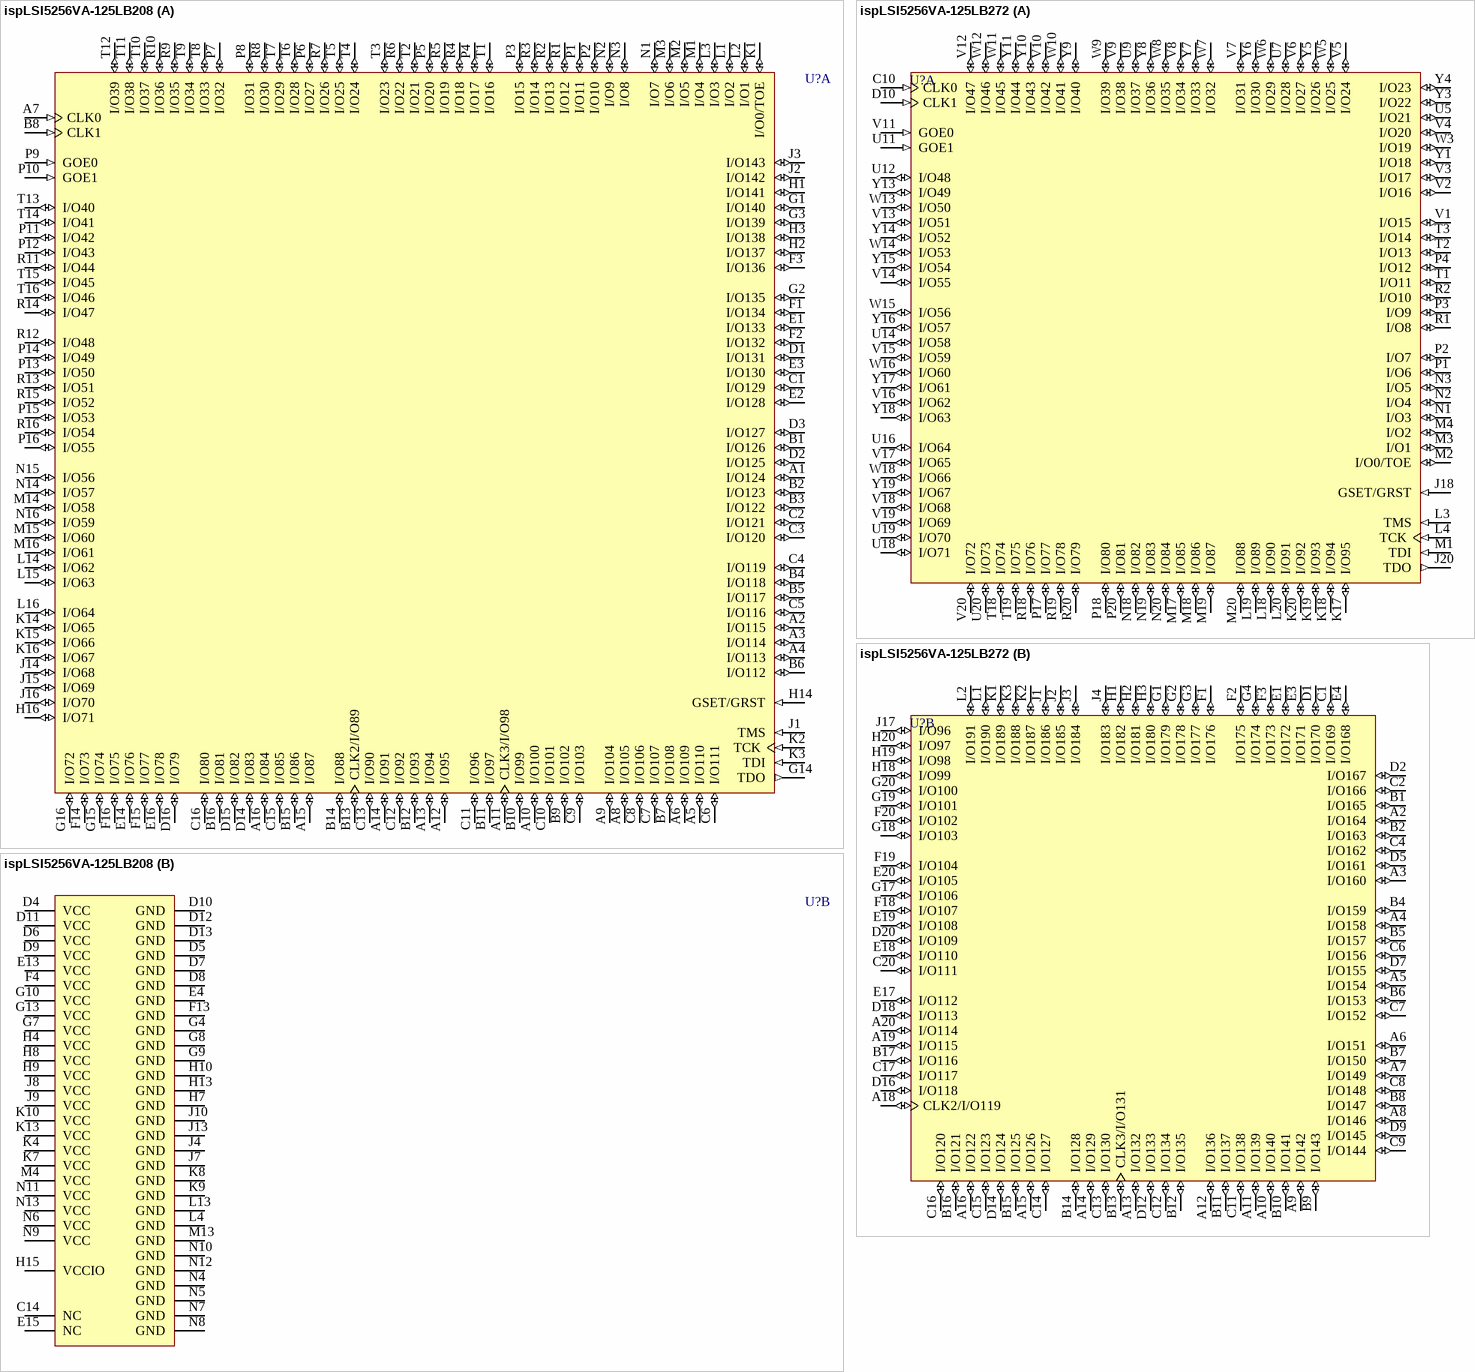
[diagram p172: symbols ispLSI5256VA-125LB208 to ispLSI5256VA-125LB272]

## ispLSI5256VA-125LB208
designator U?
In-System Programmable 3.3V SuperWIDE High Density PLD
footprint fpBGA208 (BGA, 208-Leads, Body 17x17mm, Pitch 1mm)
3D model 5384VA-fpBGA208 (208-Ball Fine Pitch Ball Grid Array (fpBGA208))
part A pins: A1 I/O124 (io), A2 I/O115 (io), A3 I/O114 (io), A4 I/O113 (io), A5 I/O110 (io), A6 I/O109 (io), A7 CLK0 (in), A8 I/O105 (io), A9 I/O104 (io), A10 I/O100 (io), A11 CLK3/I/O98 (io), A12 I/O95 (io), A13 I/O94 (io), A14 I/O91 (io), A15 I/O87 (io), A16 I/O84 (io), B1 I/O126 (io), B2 I/O123 (io), B3 I/O122 (io), B4 I/O118 (io), B5 I/O117 (io), B6 I/O112 (io), B7 I/O108 (io), B8 CLK1 (in), B9 I/O102 (io), B10 I/O99 (io), B11 I/O97 (io), B12 I/O93 (io), B13 CLK2/I/O89 (io), B14 I/O88 (io), B15 I/O86 (io), B16 I/O81 (io), C1 I/O129 (io), C2 I/O121 (io), C3 I/O120 (io), C4 I/O119 (io), C5 I/O116 (io), C6 I/O111 (io), C7 I/O107 (io), C8 I/O106 (io), C9 I/O103 (io), C10 I/O101 (io), C11 I/O96 (io), C12 I/O92 (io), C13 I/O90 (io), C15 I/O85 (io), C16 I/O80 (io), D1 I/O131 (io), D2 I/O125 (io), D3 I/O127 (io), D14 I/O83 (io), D15 I/O82 (io), D16 I/O79 (io), E1 I/O133 (io), E2 I/O128 (io), E3 I/O130 (io), E14 I/O76 (io), E16 I/O78 (io), F1 I/O134 (io), F2 I/O132 (io), F3 I/O136 (io), F14 I/O73 (io), F15 I/O77 (io), F16 I/O75 (io), G1 I/O140 (io), G2 I/O135 (io), G3 I/O139 (io), G14 TDO (out), G15 I/O74 (io), G16 I/O72 (io), H1 I/O141 (io), H2 I/O137 (io), H3 I/O138 (io), H14 GSET/GRST (in), H16 I/O71 (io), J1 TMS (in), J2 I/O142 (io), J3 I/O143 (io), J14 I/O68 (io), J15 I/O69 (io), J16 I/O70 (io), K1 I/O0/TOE (io), K2 TCK (in), K3 TDI (in), K14 I/O65 (io), K15 I/O66 (io), K16 I/O67 (io), L1 I/O2 (io), L2 I/O1 (io), L3 I/O3 (io), L14 I/O62 (io), L15 I/O63 (io), L16 I/O64 (io), M1 I/O4 (io), M2 I/O5 (io), M3 I/O6 (io), M14 I/O58 (io), M15 I/O60 (io), M16 I/O61 (io), N1 I/O7 (io), N2 I/O9 (io), N3 I/O8 (io), N14 I/O57 (io), N15 I/O56 (io), N16 I/O59 (io), P1 I/O11 (io), P2 I/O10 (io), P3 I/O15 (io), P4 I/O17 (io), P5 I/O20 (io), P6 I/O27 (io), P7 I/O32 (io), P8 I/O31 (io), P9 GOE0 (in), P10 GOE1 (in), P11 I/O42 (io), P12 I/O43 (io), P13 I/O50 (io), P14 I/O49 (io), P15 I/O53 (io), P16 I/O55 (io), R1 I/O12 (io), R2 I/O13 (io), R3 I/O14 (io), R4 I/O18 (io), R5 I/O19 (io), R6 I/O22 (io), R7 I/O26 (io), R8 I/O30 (io), R9 I/O35 (io), R10 I/O36 (io), R11 I/O44 (io), R12 I/O48 (io), R13 I/O51 (io), R14 I/O47 (io), R15 I/O52 (io), R16 I/O54 (io), T1 I/O16 (io), T2 I/O21 (io), T3 I/O23 (io), T4 I/O24 (io), T5 I/O25 (io), T6 I/O28 (io), T7 I/O29 (io), T8 I/O33 (io), T9 I/O34 (io), T10 I/O37 (io), T11 I/O38 (io), T12 I/O39 (io), T13 I/O40 (io), T14 I/O41 (io), T15 I/O45 (io), T16 I/O46 (io)
part B pins: C14 NC, D4 VCC (power), D5 GND (power), D6 VCC (power), D7 GND (power), D8 GND (power), D9 VCC (power), D10 GND (power), D11 VCC (power), D12 GND (power), D13 GND (power), E4 GND (power), E13 VCC (power), E15 NC, F4 VCC (power), F13 GND (power), G4 GND (power), G7 VCC (power), G8 GND (power), G9 GND (power), G10 VCC (power), G13 VCC (power), H4 VCC (power), H7 GND (power), H8 VCC (power), H9 VCC (power), H10 GND (power), H13 GND (power), H15 VCCIO (power), J4 GND (power), J7 GND (power), J8 VCC (power), J9 VCC (power), J10 GND (power), J13 GND (power), K4 VCC (power), K7 VCC (power), K8 GND (power), K9 GND (power), K10 VCC (power), K13 VCC (power), L4 GND (power), L13 GND (power), M4 VCC (power), M13 GND (power), N4 GND (power), N5 GND (power), N6 VCC (power), N7 GND (power), N8 GND (power), N9 VCC (power), N10 GND (power), N11 VCC (power), N12 GND (power), N13 VCC (power)

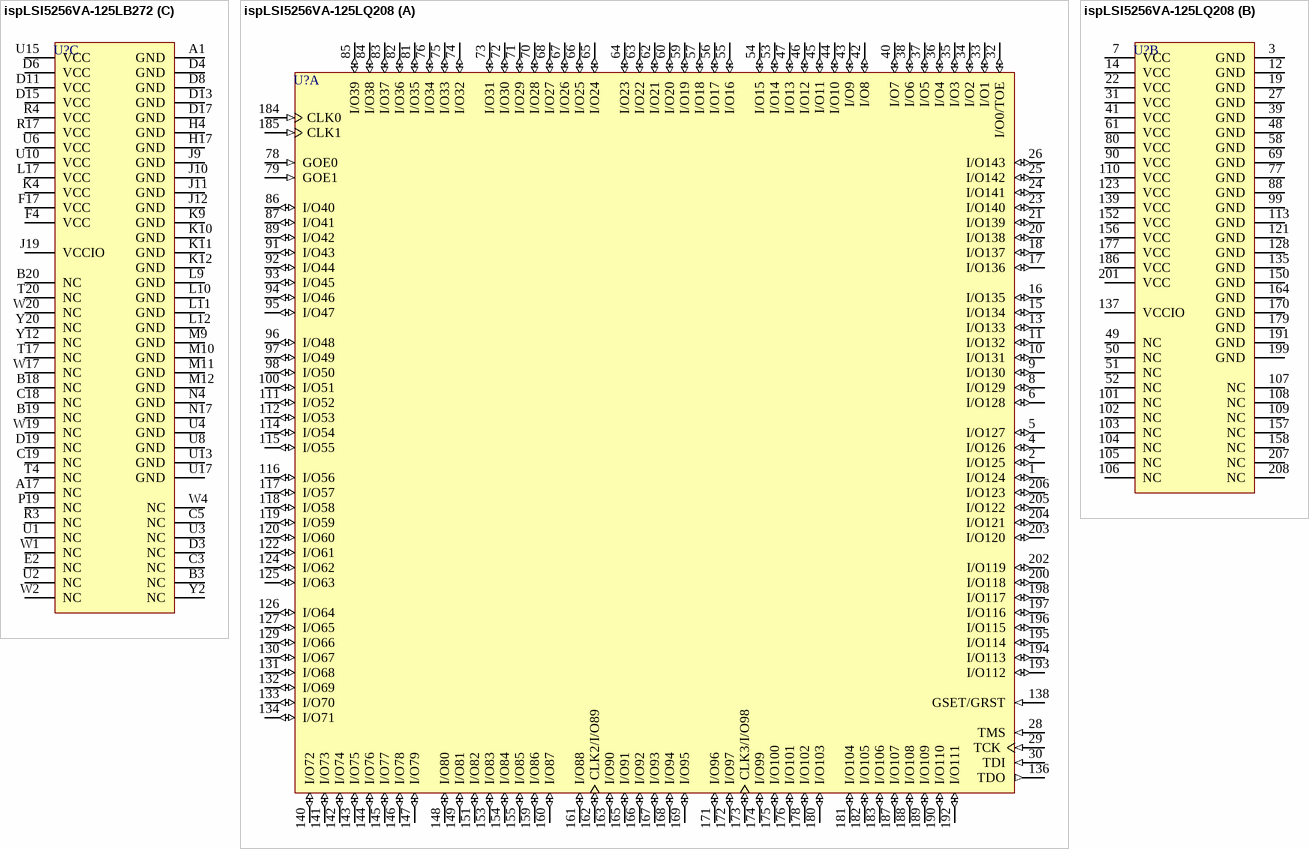
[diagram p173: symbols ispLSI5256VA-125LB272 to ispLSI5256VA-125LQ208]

## ispLSI5256VA-125LB272
designator U?
In-System Programmable 3.3V SuperWIDE High Density PLD
footprint BGA272 (BGA, 272-Leads, Body 27x27mm, Pitch 1.27mm)
3D model 5256VA-BGA272 (272-Ball Ball Grid Array (BGA272))
part A pins: C10 CLK0 (in), D10 CLK1 (in), J18 GSET/GRST (in), J20 TDO (out), K17 I/O95 (io), K18 I/O94 (io), K19 I/O93 (io), K20 I/O92 (io), L3 TMS (in), L4 TCK (in), L18 I/O90 (io), L19 I/O89 (io), L20 I/O91 (io), M1 TDI (in), M2 I/O0/TOE (io), M3 I/O1 (io), M4 I/O2 (io), M17 I/O85 (io), M18 I/O86 (io), M19 I/O87 (io), M20 I/O88 (io), N1 I/O3 (io), N2 I/O4 (io), N3 I/O5 (io), N18 I/O82 (io), N19 I/O83 (io), N20 I/O84 (io), P1 I/O6 (io), P2 I/O7 (io), P3 I/O9 (io), P4 I/O12 (io), P17 I/O77 (io), P18 I/O80 (io), P20 I/O81 (io), R1 I/O8 (io), R2 I/O10 (io), R18 I/O76 (io), R19 I/O78 (io), R20 I/O79 (io), T1 I/O11 (io), T2 I/O13 (io), T3 I/O14 (io), T18 I/O74 (io), T19 I/O75 (io), U5 I/O21 (io), U7 I/O28 (io), U9 I/O37 (io), U11 GOE1 (in), U12 I/O48 (io), U14 I/O58 (io), U16 I/O64 (io), U18 I/O71 (io), U19 I/O70 (io), U20 I/O73 (io), V1 I/O15 (io), V2 I/O16 (io), V3 I/O17 (io), V4 I/O20 (io), V5 I/O24 (io), V6 I/O27 (io), V7 I/O31 (io), V8 I/O34 (io), V9 I/O38 (io), V10 I/O42 (io), V11 GOE0 (in), V12 I/O47 (io), V13 I/O51 (io), V14 I/O55 (io), V15 I/O59 (io), V16 I/O62 (io), V17 I/O65 (io), V18 I/O68 (io), V19 I/O69 (io), V20 I/O72 (io), W3 I/O19 (io), W5 I/O25 (io), W6 I/O29 (io), W7 I/O32 (io), W8 I/O35 (io), W9 I/O39 (io), W10 I/O41 (io), W11 I/O45 (io), W12 I/O46 (io), W13 I/O50 (io), W14 I/O53 (io), W15 I/O56 (io), W16 I/O60 (io), W18 I/O66 (io), Y1 I/O18 (io), Y3 I/O22 (io), Y4 I/O23 (io), Y5 I/O26 (io), Y6 I/O30 (io), Y7 I/O33 (io), Y8 I/O36 (io), Y9 I/O40 (io), Y10 I/O43 (io), Y11 I/O44 (io), Y13 I/O49 (io), Y14 I/O52 (io), Y15 I/O54 (io), Y16 I/O57 (io), Y17 I/O61 (io), Y18 I/O63 (io), Y19 I/O67 (io)
part B pins: A2 I/O164 (io), A3 I/O160 (io), A4 I/O158 (io), A5 I/O154 (io), A6 I/O151 (io), A7 I/O149 (io), A8 I/O146 (io), A9 I/O142 (io), A10 I/O140 (io), A11 I/O139 (io), A12 I/O136 (io), A13 I/O132 (io), A14 I/O129 (io), A15 I/O126 (io), A16 I/O122 (io), A18 CLK2/I/O119 (io), A19 I/O115 (io), A20 I/O114 (io), B1 I/O165 (io), B2 I/O163 (io), B4 I/O159 (io), B5 I/O157 (io), B6 I/O153 (io), B7 I/O150 (io), B8 I/O147 (io), B9 I/O143 (io), B10 I/O141 (io), B11 I/O137 (io), B12 I/O135 (io), B13 CLK3/I/O131 (io), B14 I/O128 (io), B15 I/O125 (io), B16 I/O121 (io), B17 I/O116 (io), C1 I/O169 (io), C2 I/O166 (io), C4 I/O162 (io), C6 I/O156 (io), C7 I/O152 (io), C8 I/O148 (io), C9 I/O144 (io), C11 I/O138 (io), C12 I/O134 (io), C13 I/O130 (io), C14 I/O127 (io), C15 I/O123 (io), C16 I/O120 (io), C17 I/O117 (io), C20 I/O111 (io), D1 I/O170 (io), D2 I/O167 (io), D5 I/O161 (io), D7 I/O155 (io), D9 I/O145 (io), D12 I/O133 (io), D14 I/O124 (io), D16 I/O118 (io), D18 I/O113 (io), D20 I/O109 (io), E1 I/O172 (io), E3 I/O171 (io), E4 I/O168 (io), E17 I/O112 (io), E18 I/O110 (io), E19 I/O108 (io), E20 I/O105 (io), F1 I/O176 (io), F2 I/O175 (io), F3 I/O173 (io), F18 I/O107 (io), F19 I/O104 (io), F20 I/O102 (io), G1 I/O179 (io), G2 I/O178 (io), G3 I/O177 (io), G4 I/O174 (io), G17 I/O106 (io), G18 I/O103 (io), G19 I/O101 (io), G20 I/O100 (io), H1 I/O182 (io), H2 I/O181 (io), H3 I/O180 (io), H18 I/O99 (io), H19 I/O98 (io), H20 I/O97 (io), J1 I/O186 (io), J2 I/O185 (io), J3 I/O184 (io), J4 I/O183 (io), J17 I/O96 (io), K1 I/O189 (io), K2 I/O187 (io), K3 I/O188 (io), L1 I/O190 (io), L2 I/O191 (io)
part C pins: A1 GND (power), A17 NC, B3 NC, B18 NC, B19 NC, B20 NC, C3 NC, C5 NC, C18 NC, C19 NC, D3 NC, D4 GND (power), D6 VCC (power), D8 GND (power), D11 VCC (power), D13 GND (power), D15 VCC (power), D17 GND (power), D19 NC, E2 NC, F4 VCC (power), F17 VCC (power), H4 GND (power), H17 GND (power), J9 GND (power), J10 GND (power), J11 GND (power), J12 GND (power), J19 VCCIO (power), K4 VCC (power), K9 GND (power), K10 GND (power), K11 GND (power), K12 GND (power), L9 GND (power), L10 GND (power), L11 GND (power), L12 GND (power), L17 VCC (power), M9 GND (power), M10 GND (power), M11 GND (power), M12 GND (power), N4 GND (power), N17 GND (power), P19 NC, R3 NC, R4 VCC (power), R17 VCC (power), T4 NC, T17 NC, T20 NC, U1 NC, U2 NC, U3 NC, U4 GND (power), U6 VCC (power), U8 GND (power), U10 VCC (power), U13 GND (power), U15 VCC (power), U17 GND (power), W1 NC, W2 NC, W4 NC, W17 NC, W19 NC, W20 NC, Y2 NC, Y12 NC, Y20 NC

## ispLSI5256VA-125LQ208
designator U?
In-System Programmable 3.3V SuperWIDE High Density PLD
footprint PQFP208_N (Shrink QFP, 208-Leads, Body 28x28mm, Pitch 0.5mm, IPC Medium Density)
footprint PQFP208_L (Shrink QFP, 208-Leads, Body 28x28mm, Pitch 0.5mm, IPC High Density)
footprint PQFP208_M (Shrink QFP, 208-Leads, Body 28x28mm, Pitch 0.5mm, IPC Low Density)
3D model 5256VA-PQFP208 (208-Pin Plastic Quad Flat Pack (PQFP208))
part A pins: 1 I/O124 (io), 2 I/O125 (io), 4 I/O126 (io), 5 I/O127 (io), 6 I/O128 (io), 8 I/O129 (io), 9 I/O130 (io), 10 I/O131 (io), 11 I/O132 (io), 13 I/O133 (io), 15 I/O134 (io), 16 I/O135 (io), 17 I/O136 (io), 18 I/O137 (io), 20 I/O138 (io), 21 I/O139 (io), 23 I/O140 (io), 24 I/O141 (io), 25 I/O142 (io), 26 I/O143 (io), 28 TMS (in), 29 TCK (in), 30 TDI (in), 32 I/O0/TOE (io), 33 I/O1 (io), 34 I/O2 (io), 35 I/O3 (io), 36 I/O4 (io), 37 I/O5 (io), 38 I/O6 (io), 40 I/O7 (io), 42 I/O8 (io), 43 I/O9 (io), 44 I/O10 (io), 45 I/O11 (io), 46 I/O12 (io), 47 I/O13 (io), 53 I/O14 (io), 54 I/O15 (io), 55 I/O16 (io), 56 I/O17 (io), 57 I/O18 (io), 59 I/O19 (io), 60 I/O20 (io), 62 I/O21 (io), 63 I/O22 (io), 64 I/O23 (io), 65 I/O24 (io), 66 I/O25 (io), 67 I/O26 (io), 68 I/O27 (io), 70 I/O28 (io), 71 I/O29 (io), 72 I/O30 (io), 73 I/O31 (io), 74 I/O32 (io), 75 I/O33 (io), 76 I/O34 (io), 78 GOE0 (in), 79 GOE1 (in), 81 I/O35 (io), 82 I/O36 (io), 83 I/O37 (io), 84 I/O38 (io), 85 I/O39 (io), 86 I/O40 (io), 87 I/O41 (io), 89 I/O42 (io), 91 I/O43 (io), 92 I/O44 (io), 93 I/O45 (io), 94 I/O46 (io), 95 I/O47 (io), 96 I/O48 (io), 97 I/O49 (io), 98 I/O50 (io), 100 I/O51 (io), 111 I/O52 (io), 112 I/O53 (io), 114 I/O54 (io), 115 I/O55 (io), 116 I/O56 (io), 117 I/O57 (io), 118 I/O58 (io), 119 I/O59 (io), 120 I/O60 (io), 122 I/O61 (io), 124 I/O62 (io), 125 I/O63 (io), 126 I/O64 (io), 127 I/O65 (io), 129 I/O66 (io), 130 I/O67 (io), 131 I/O68 (io), 132 I/O69 (io), 133 I/O70 (io), 134 I/O71 (io), 136 TDO (out), 138 GSET/GRST (in), 140 I/O72 (io), 141 I/O73 (io), 142 I/O74 (io), 143 I/O75 (io), 144 I/O76 (io), 145 I/O77 (io), 146 I/O78 (io), 147 I/O79 (io), 148 I/O80 (io), 149 I/O81 (io), 151 I/O82 (io), 153 I/O83 (io), 154 I/O84 (io), 155 I/O85 (io), 159 I/O86 (io), 160 I/O87 (io), 161 I/O88 (io), 162 CLK2/I/O89 (io), 163 I/O90 (io), 165 I/O91 (io), 166 I/O92 (io), 167 I/O93 (io), 168 I/O94 (io), 169 I/O95 (io), 171 I/O96 (io), 172 I/O97 (io), 173 CLK3/I/O98 (io), 174 I/O99 (io), 175 I/O100 (io), 176 I/O101 (io), 178 I/O102 (io), 180 I/O103 (io), 181 I/O104 (io), 182 I/O105 (io), 183 I/O106 (io), 184 CLK0 (in), 185 CLK1 (in), 187 I/O107 (io), 188 I/O108 (io), 189 I/O109 (io), 190 I/O110 (io), 192 I/O111 (io), 193 I/O112 (io), 194 I/O113 (io), 195 I/O114 (io), 196 I/O115 (io), 197 I/O116 (io), 198 I/O117 (io), 200 I/O118 (io), 202 I/O119 (io), 203 I/O120 (io), 204 I/O121 (io), 205 I/O122 (io), 206 I/O123 (io)
part B pins: 3 GND (power), 7 VCC (power), 12 GND (power), 14 VCC (power), 19 GND (power), 22 VCC (power), 27 GND (power), 31 VCC (power), 39 GND (power), 41 VCC (power), 48 GND (power), 49 NC, 50 NC, 51 NC, 52 NC, 58 GND (power), 61 VCC (power), 69 GND (power), 77 GND (power), 80 VCC (power), 88 GND (power), 90 VCC (power), 99 GND (power), 101 NC, 102 NC, 103 NC, 104 NC, 105 NC, 106 NC, 107 NC, 108 NC, 109 NC, 110 VCC (power), 113 GND (power), 121 GND (power), 123 VCC (power), 128 GND (power), 135 GND (power), 137 VCCIO (power), 139 VCC (power), 150 GND (power), 152 VCC (power), 156 VCC (power), 157 NC, 158 NC, 164 GND (power), 170 GND (power), 177 VCC (power), 179 GND (power), 186 VCC (power), 191 GND (power), 199 GND (power), 201 VCC (power), 207 NC, 208 NC

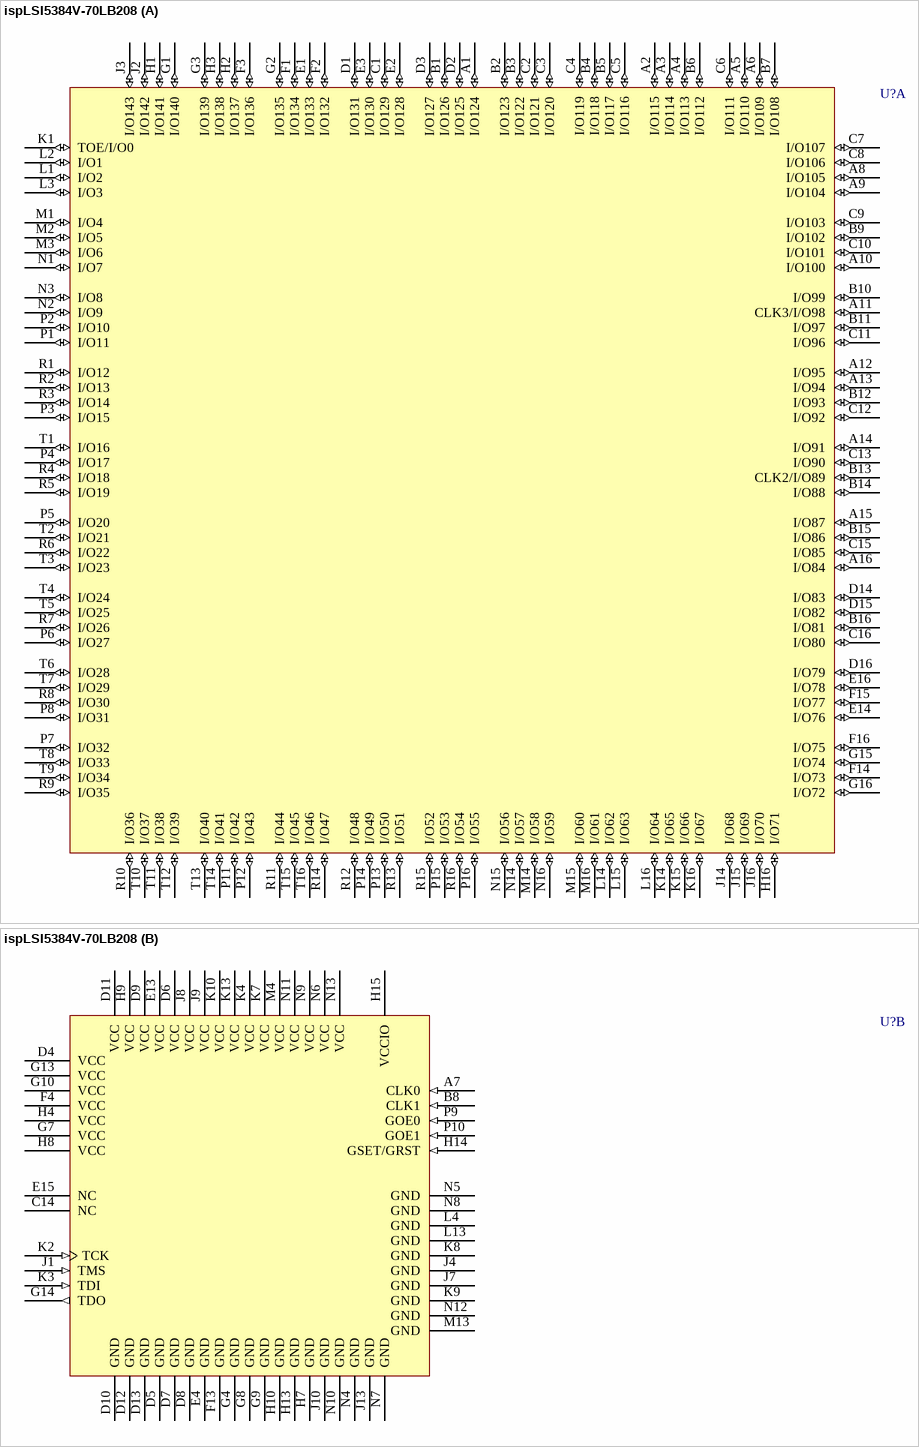
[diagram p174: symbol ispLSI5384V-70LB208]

## ispLSI5384V-70LB208
designator U?
In-System Programmable 3.3V SuperWIDE High-Density PLD; Note: I/O89 is multiplexed with CLK2; I/O98 is multiplexed with CLK3; I/O0 is multiplexed with TOE.
footprint fpBGA208 (BGA, 208-Leads, Body 17x17mm, Pitch 1mm)
3D model 5384V-fpBGA208 (208-Ball Fine Pitch Ball Grid Array (fpBGA208))
part A pins: A1 I/O124 (io), A2 I/O115 (io), A3 I/O114 (io), A4 I/O113 (io), A5 I/O110 (io), A6 I/O109 (io), A8 I/O105 (io), A9 I/O104 (io), A10 I/O100 (io), A11 CLK3/I/O98 (io), A12 I/O95 (io), A13 I/O94 (io), A14 I/O91 (io), A15 I/O87 (io), A16 I/O84 (io), B1 I/O126 (io), B2 I/O123 (io), B3 I/O122 (io), B4 I/O118 (io), B5 I/O117 (io), B6 I/O112 (io), B7 I/O108 (io), B9 I/O102 (io), B10 I/O99 (io), B11 I/O97 (io), B12 I/O93 (io), B13 CLK2/I/O89 (io), B14 I/O88 (io), B15 I/O86 (io), B16 I/O81 (io), C1 I/O129 (io), C2 I/O121 (io), C3 I/O120 (io), C4 I/O119 (io), C5 I/O116 (io), C6 I/O111 (io), C7 I/O107 (io), C8 I/O106 (io), C9 I/O103 (io), C10 I/O101 (io), C11 I/O96 (io), C12 I/O92 (io), C13 I/O90 (io), C15 I/O85 (io), C16 I/O80 (io), D1 I/O131 (io), D2 I/O125 (io), D3 I/O127 (io), D14 I/O83 (io), D15 I/O82 (io), D16 I/O79 (io), E1 I/O133 (io), E2 I/O128 (io), E3 I/O130 (io), E14 I/O76 (io), E16 I/O78 (io), F1 I/O134 (io), F2 I/O132 (io), F3 I/O136 (io), F14 I/O73 (io), F15 I/O77 (io), F16 I/O75 (io), G1 I/O140 (io), G2 I/O135 (io), G3 I/O139 (io), G15 I/O74 (io), G16 I/O72 (io), H1 I/O141 (io), H2 I/O137 (io), H3 I/O138 (io), H16 I/O71 (io), J2 I/O142 (io), J3 I/O143 (io), J14 I/O68 (io), J15 I/O69 (io), J16 I/O70 (io), K1 TOE/I/O0 (io), K14 I/O65 (io), K15 I/O66 (io), K16 I/O67 (io), L1 I/O2 (io), L2 I/O1 (io), L3 I/O3 (io), L14 I/O62 (io), L15 I/O63 (io), L16 I/O64 (io), M1 I/O4 (io), M2 I/O5 (io), M3 I/O6 (io), M14 I/O58 (io), M15 I/O60 (io), M16 I/O61 (io), N1 I/O7 (io), N2 I/O9 (io), N3 I/O8 (io), N14 I/O57 (io), N15 I/O56 (io), N16 I/O59 (io), P1 I/O11 (io), P2 I/O10 (io), P3 I/O15 (io), P4 I/O17 (io), P5 I/O20 (io), P6 I/O27 (io), P7 I/O32 (io), P8 I/O31 (io), P11 I/O42 (io), P12 I/O43 (io), P13 I/O50 (io), P14 I/O49 (io), P15 I/O53 (io), P16 I/O55 (io), R1 I/O12 (io), R2 I/O13 (io), R3 I/O14 (io), R4 I/O18 (io), R5 I/O19 (io), R6 I/O22 (io), R7 I/O26 (io), R8 I/O30 (io), R9 I/O35 (io), R10 I/O36 (io), R11 I/O44 (io), R12 I/O48 (io), R13 I/O51 (io), R14 I/O47 (io), R15 I/O52 (io), R16 I/O54 (io), T1 I/O16 (io), T2 I/O21 (io), T3 I/O23 (io), T4 I/O24 (io), T5 I/O25 (io), T6 I/O28 (io), T7 I/O29 (io), T8 I/O33 (io), T9 I/O34 (io), T10 I/O37 (io), T11 I/O38 (io), T12 I/O39 (io), T13 I/O40 (io), T14 I/O41 (io), T15 I/O45 (io), T16 I/O46 (io)
part B pins: A7 CLK0 (in), B8 CLK1 (in), C14 NC, D4 VCC (power), D5 GND (power), D6 VCC (power), D7 GND (power), D8 GND (power), D9 VCC (power), D10 GND (power), D11 VCC (power), D12 GND (power), D13 GND (power), E4 GND (power), E13 VCC (power), E15 NC, F4 VCC (power), F13 GND (power), G4 GND (power), G7 VCC (power), G8 GND (power), G9 GND (power), G10 VCC (power), G13 VCC (power), G14 TDO (out), H4 VCC (power), H7 GND (power), H8 VCC (power), H9 VCC (power), H10 GND (power), H13 GND (power), H14 GSET/GRST (in), H15 VCCIO (power), J1 TMS (in), J4 GND (power), J7 GND (power), J8 VCC (power), J9 VCC (power), J10 GND (power), J13 GND (power), K2 TCK (in), K3 TDI (in), K4 VCC (power), K7 VCC (power), K8 GND (power), K9 GND (power), K10 VCC (power), K13 VCC (power), L4 GND (power), L13 GND (power), M4 VCC (power), M13 GND (power), N4 GND (power), N5 GND (power), N6 VCC (power), N7 GND (power), N8 GND (power), N9 VCC (power), N10 GND (power), N11 VCC (power), N12 GND (power), N13 VCC (power), P9 GOE0 (in), P10 GOE1 (in)

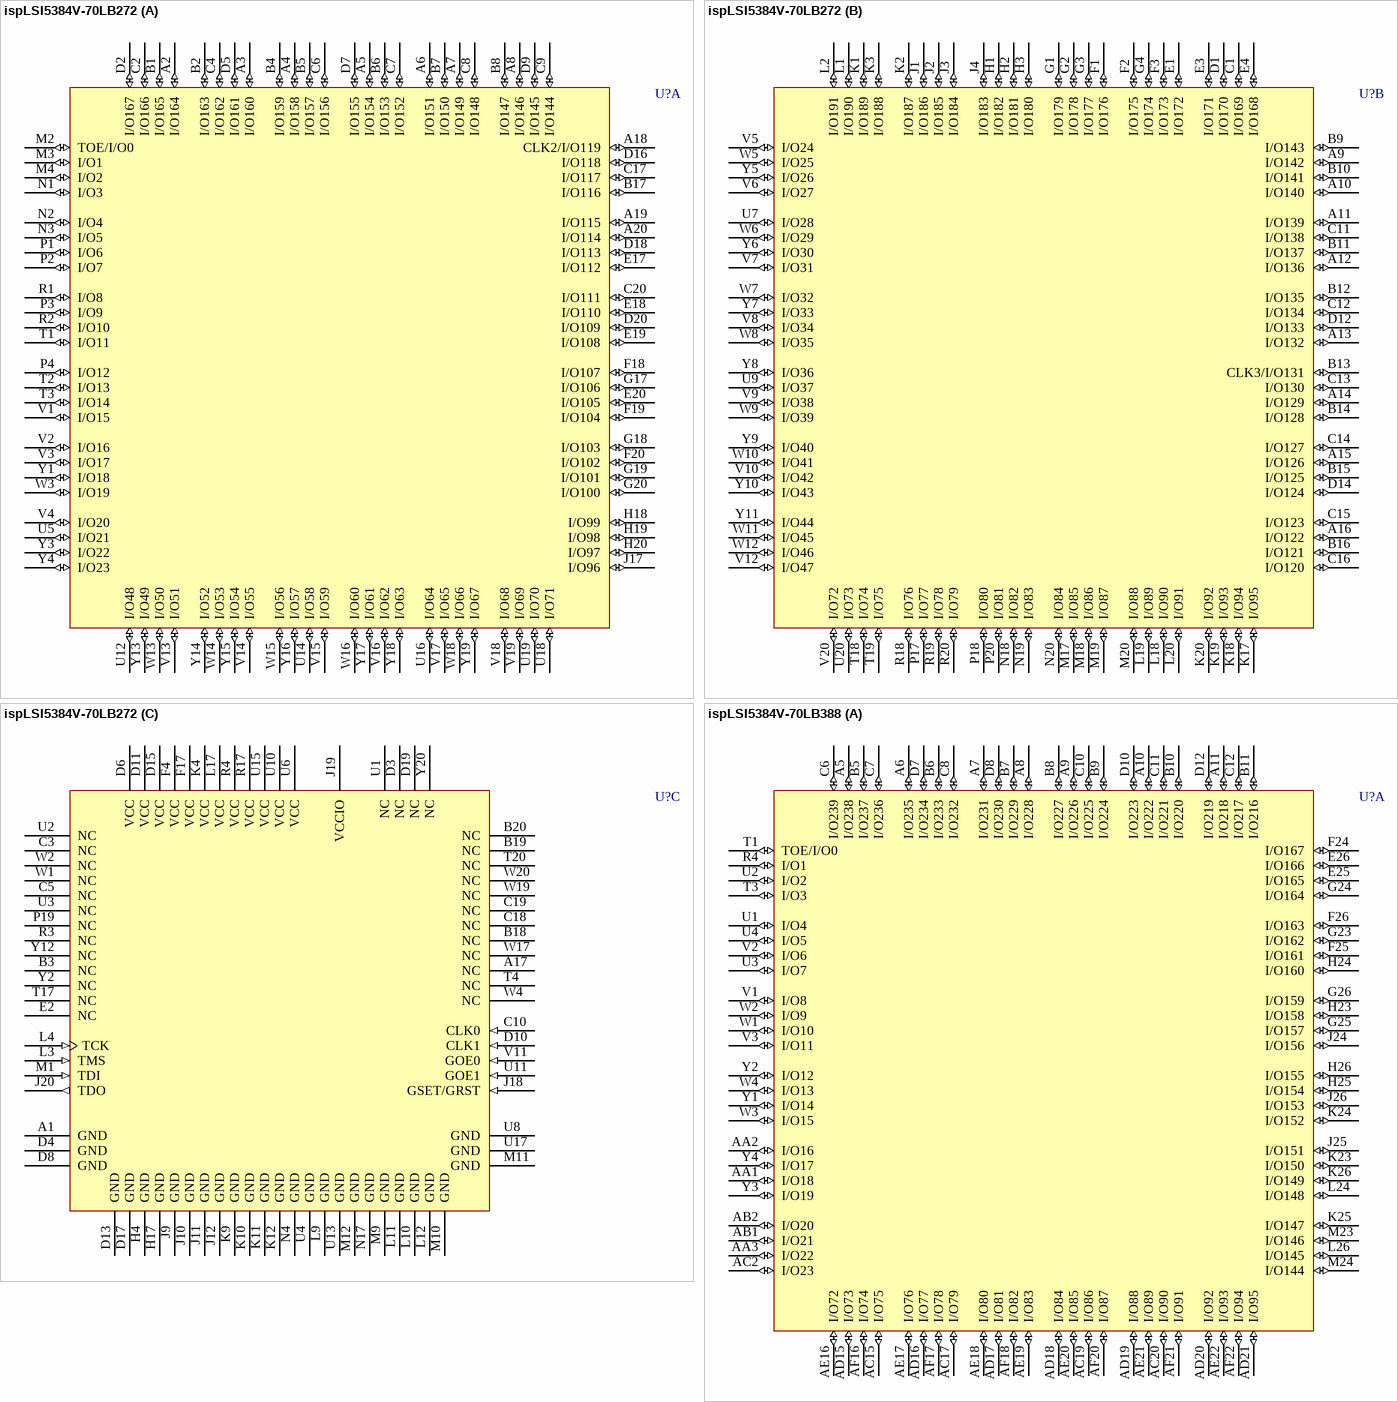
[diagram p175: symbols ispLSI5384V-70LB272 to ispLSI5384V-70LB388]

## ispLSI5384V-70LB272
designator U?
In-System Programmable 3.3V SuperWIDE High-Density PLD; Note: I/O119 is multiplexed with CLK2; I/O131 is multiplexed with CLK3; I/O0 is multiplexed with TOE.
footprint BGA272 (BGA, 272-Leads, Body 27x27mm, Pitch 1.27mm)
3D model 5384V-BGA272 (272-Ball Ball Grid Array (BGA272))
part A pins: A2 I/O164 (io), A3 I/O160 (io), A4 I/O158 (io), A5 I/O154 (io), A6 I/O151 (io), A7 I/O149 (io), A8 I/O146 (io), A18 CLK2/I/O119 (io), A19 I/O115 (io), A20 I/O114 (io), B1 I/O165 (io), B2 I/O163 (io), B4 I/O159 (io), B5 I/O157 (io), B6 I/O153 (io), B7 I/O150 (io), B8 I/O147 (io), B17 I/O116 (io), C2 I/O166 (io), C4 I/O162 (io), C6 I/O156 (io), C7 I/O152 (io), C8 I/O148 (io), C9 I/O144 (io), C17 I/O117 (io), C20 I/O111 (io), D2 I/O167 (io), D5 I/O161 (io), D7 I/O155 (io), D9 I/O145 (io), D16 I/O118 (io), D18 I/O113 (io), D20 I/O109 (io), E17 I/O112 (io), E18 I/O110 (io), E19 I/O108 (io), E20 I/O105 (io), F18 I/O107 (io), F19 I/O104 (io), F20 I/O102 (io), G17 I/O106 (io), G18 I/O103 (io), G19 I/O101 (io), G20 I/O100 (io), H18 I/O99 (io), H19 I/O98 (io), H20 I/O97 (io), J17 I/O96 (io), M2 TOE/I/O0 (io), M3 I/O1 (io), M4 I/O2 (io), N1 I/O3 (io), N2 I/O4 (io), N3 I/O5 (io), P1 I/O6 (io), P2 I/O7 (io), P3 I/O9 (io), P4 I/O12 (io), R1 I/O8 (io), R2 I/O10 (io), T1 I/O11 (io), T2 I/O13 (io), T3 I/O14 (io), U5 I/O21 (io), U12 I/O48 (io), U14 I/O58 (io), U16 I/O64 (io), U18 I/O71 (io), U19 I/O70 (io), V1 I/O15 (io), V2 I/O16 (io), V3 I/O17 (io), V4 I/O20 (io), V13 I/O51 (io), V14 I/O55 (io), V15 I/O59 (io), V16 I/O62 (io), V17 I/O65 (io), V18 I/O68 (io), V19 I/O69 (io), W3 I/O19 (io), W13 I/O50 (io), W14 I/O53 (io), W15 I/O56 (io), W16 I/O60 (io), W18 I/O66 (io), Y1 I/O18 (io), Y3 I/O22 (io), Y4 I/O23 (io), Y13 I/O49 (io), Y14 I/O52 (io), Y15 I/O54 (io), Y16 I/O57 (io), Y17 I/O61 (io), Y18 I/O63 (io), Y19 I/O67 (io)
part B pins: A9 I/O142 (io), A10 I/O140 (io), A11 I/O139 (io), A12 I/O136 (io), A13 I/O132 (io), A14 I/O129 (io), A15 I/O126 (io), A16 I/O122 (io), B9 I/O143 (io), B10 I/O141 (io), B11 I/O137 (io), B12 I/O135 (io), B13 CLK3/I/O131 (io), B14 I/O128 (io), B15 I/O125 (io), B16 I/O121 (io), C1 I/O169 (io), C11 I/O138 (io), C12 I/O134 (io), C13 I/O130 (io), C14 I/O127 (io), C15 I/O123 (io), C16 I/O120 (io), D1 I/O170 (io), D12 I/O133 (io), D14 I/O124 (io), E1 I/O172 (io), E3 I/O171 (io), E4 I/O168 (io), F1 I/O176 (io), F2 I/O175 (io), F3 I/O173 (io), G1 I/O179 (io), G2 I/O178 (io), G3 I/O177 (io), G4 I/O174 (io), H1 I/O182 (io), H2 I/O181 (io), H3 I/O180 (io), J1 I/O186 (io), J2 I/O185 (io), J3 I/O184 (io), J4 I/O183 (io), K1 I/O189 (io), K2 I/O187 (io), K3 I/O188 (io), K17 I/O95 (io), K18 I/O94 (io), K19 I/O93 (io), K20 I/O92 (io), L1 I/O190 (io), L2 I/O191 (io), L18 I/O90 (io), L19 I/O89 (io), L20 I/O91 (io), M17 I/O85 (io), M18 I/O86 (io), M19 I/O87 (io), M20 I/O88 (io), N18 I/O82 (io), N19 I/O83 (io), N20 I/O84 (io), P17 I/O77 (io), P18 I/O80 (io), P20 I/O81 (io), R18 I/O76 (io), R19 I/O78 (io), R20 I/O79 (io), T18 I/O74 (io), T19 I/O75 (io), U7 I/O28 (io), U9 I/O37 (io), U20 I/O73 (io), V5 I/O24 (io), V6 I/O27 (io), V7 I/O31 (io), V8 I/O34 (io), V9 I/O38 (io), V10 I/O42 (io), V12 I/O47 (io), V20 I/O72 (io), W5 I/O25 (io), W6 I/O29 (io), W7 I/O32 (io), W8 I/O35 (io), W9 I/O39 (io), W10 I/O41 (io), W11 I/O45 (io), W12 I/O46 (io), Y5 I/O26 (io), Y6 I/O30 (io), Y7 I/O33 (io), Y8 I/O36 (io), Y9 I/O40 (io), Y10 I/O43 (io), Y11 I/O44 (io)
part C pins: A1 GND (power), A17 NC, B3 NC, B18 NC, B19 NC, B20 NC, C3 NC, C5 NC, C10 CLK0 (in), C18 NC, C19 NC, D3 NC, D4 GND (power), D6 VCC (power), D8 GND (power), D10 CLK1 (in), D11 VCC (power), D13 GND (power), D15 VCC (power), D17 GND (power), D19 NC, E2 NC, F4 VCC (power), F17 VCC (power), H4 GND (power), H17 GND (power), J9 GND (power), J10 GND (power), J11 GND (power), J12 GND (power), J18 GSET/GRST (in), J19 VCCIO (power), J20 TDO (out), K4 VCC (power), K9 GND (power), K10 GND (power), K11 GND (power), K12 GND (power), L3 TMS (in), L4 TCK (in), L9 GND (power), L10 GND (power), L11 GND (power), L12 GND (power), L17 VCC (power), M1 TDI (in), M9 GND (power), M10 GND (power), M11 GND (power), M12 GND (power), N4 GND (power), N17 GND (power), P19 NC, R3 NC, R4 VCC (power), R17 VCC (power), T4 NC, T17 NC, T20 NC, U1 NC, U2 NC, U3 NC, U4 GND (power), U6 VCC (power), U8 GND (power), U10 VCC (power), U11 GOE1 (in), U13 GND (power), U15 VCC (power), U17 GND (power), V11 GOE0 (in), W1 NC, W2 NC, W4 NC, W17 NC, W19 NC, W20 NC, Y2 NC, Y12 NC, Y20 NC

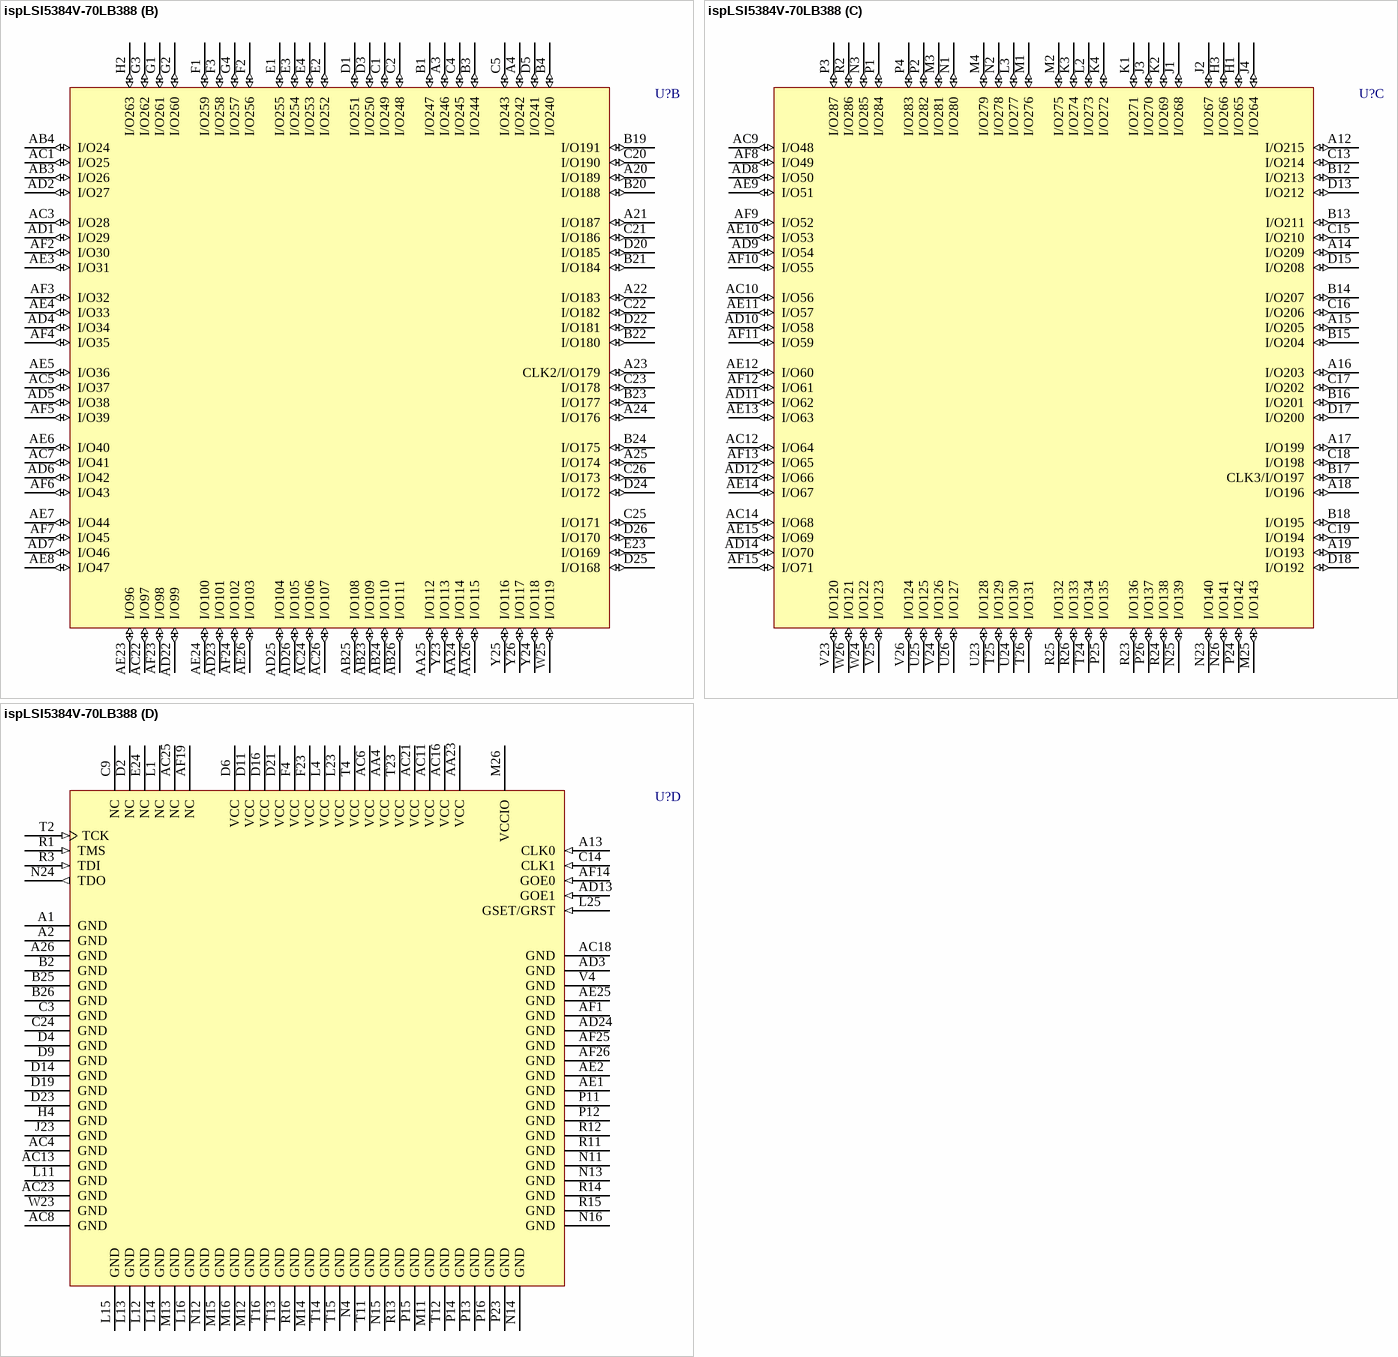
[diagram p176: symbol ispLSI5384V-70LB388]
